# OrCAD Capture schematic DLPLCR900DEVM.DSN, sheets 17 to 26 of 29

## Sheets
17 P14-Master Ext Flash Intf: size A3
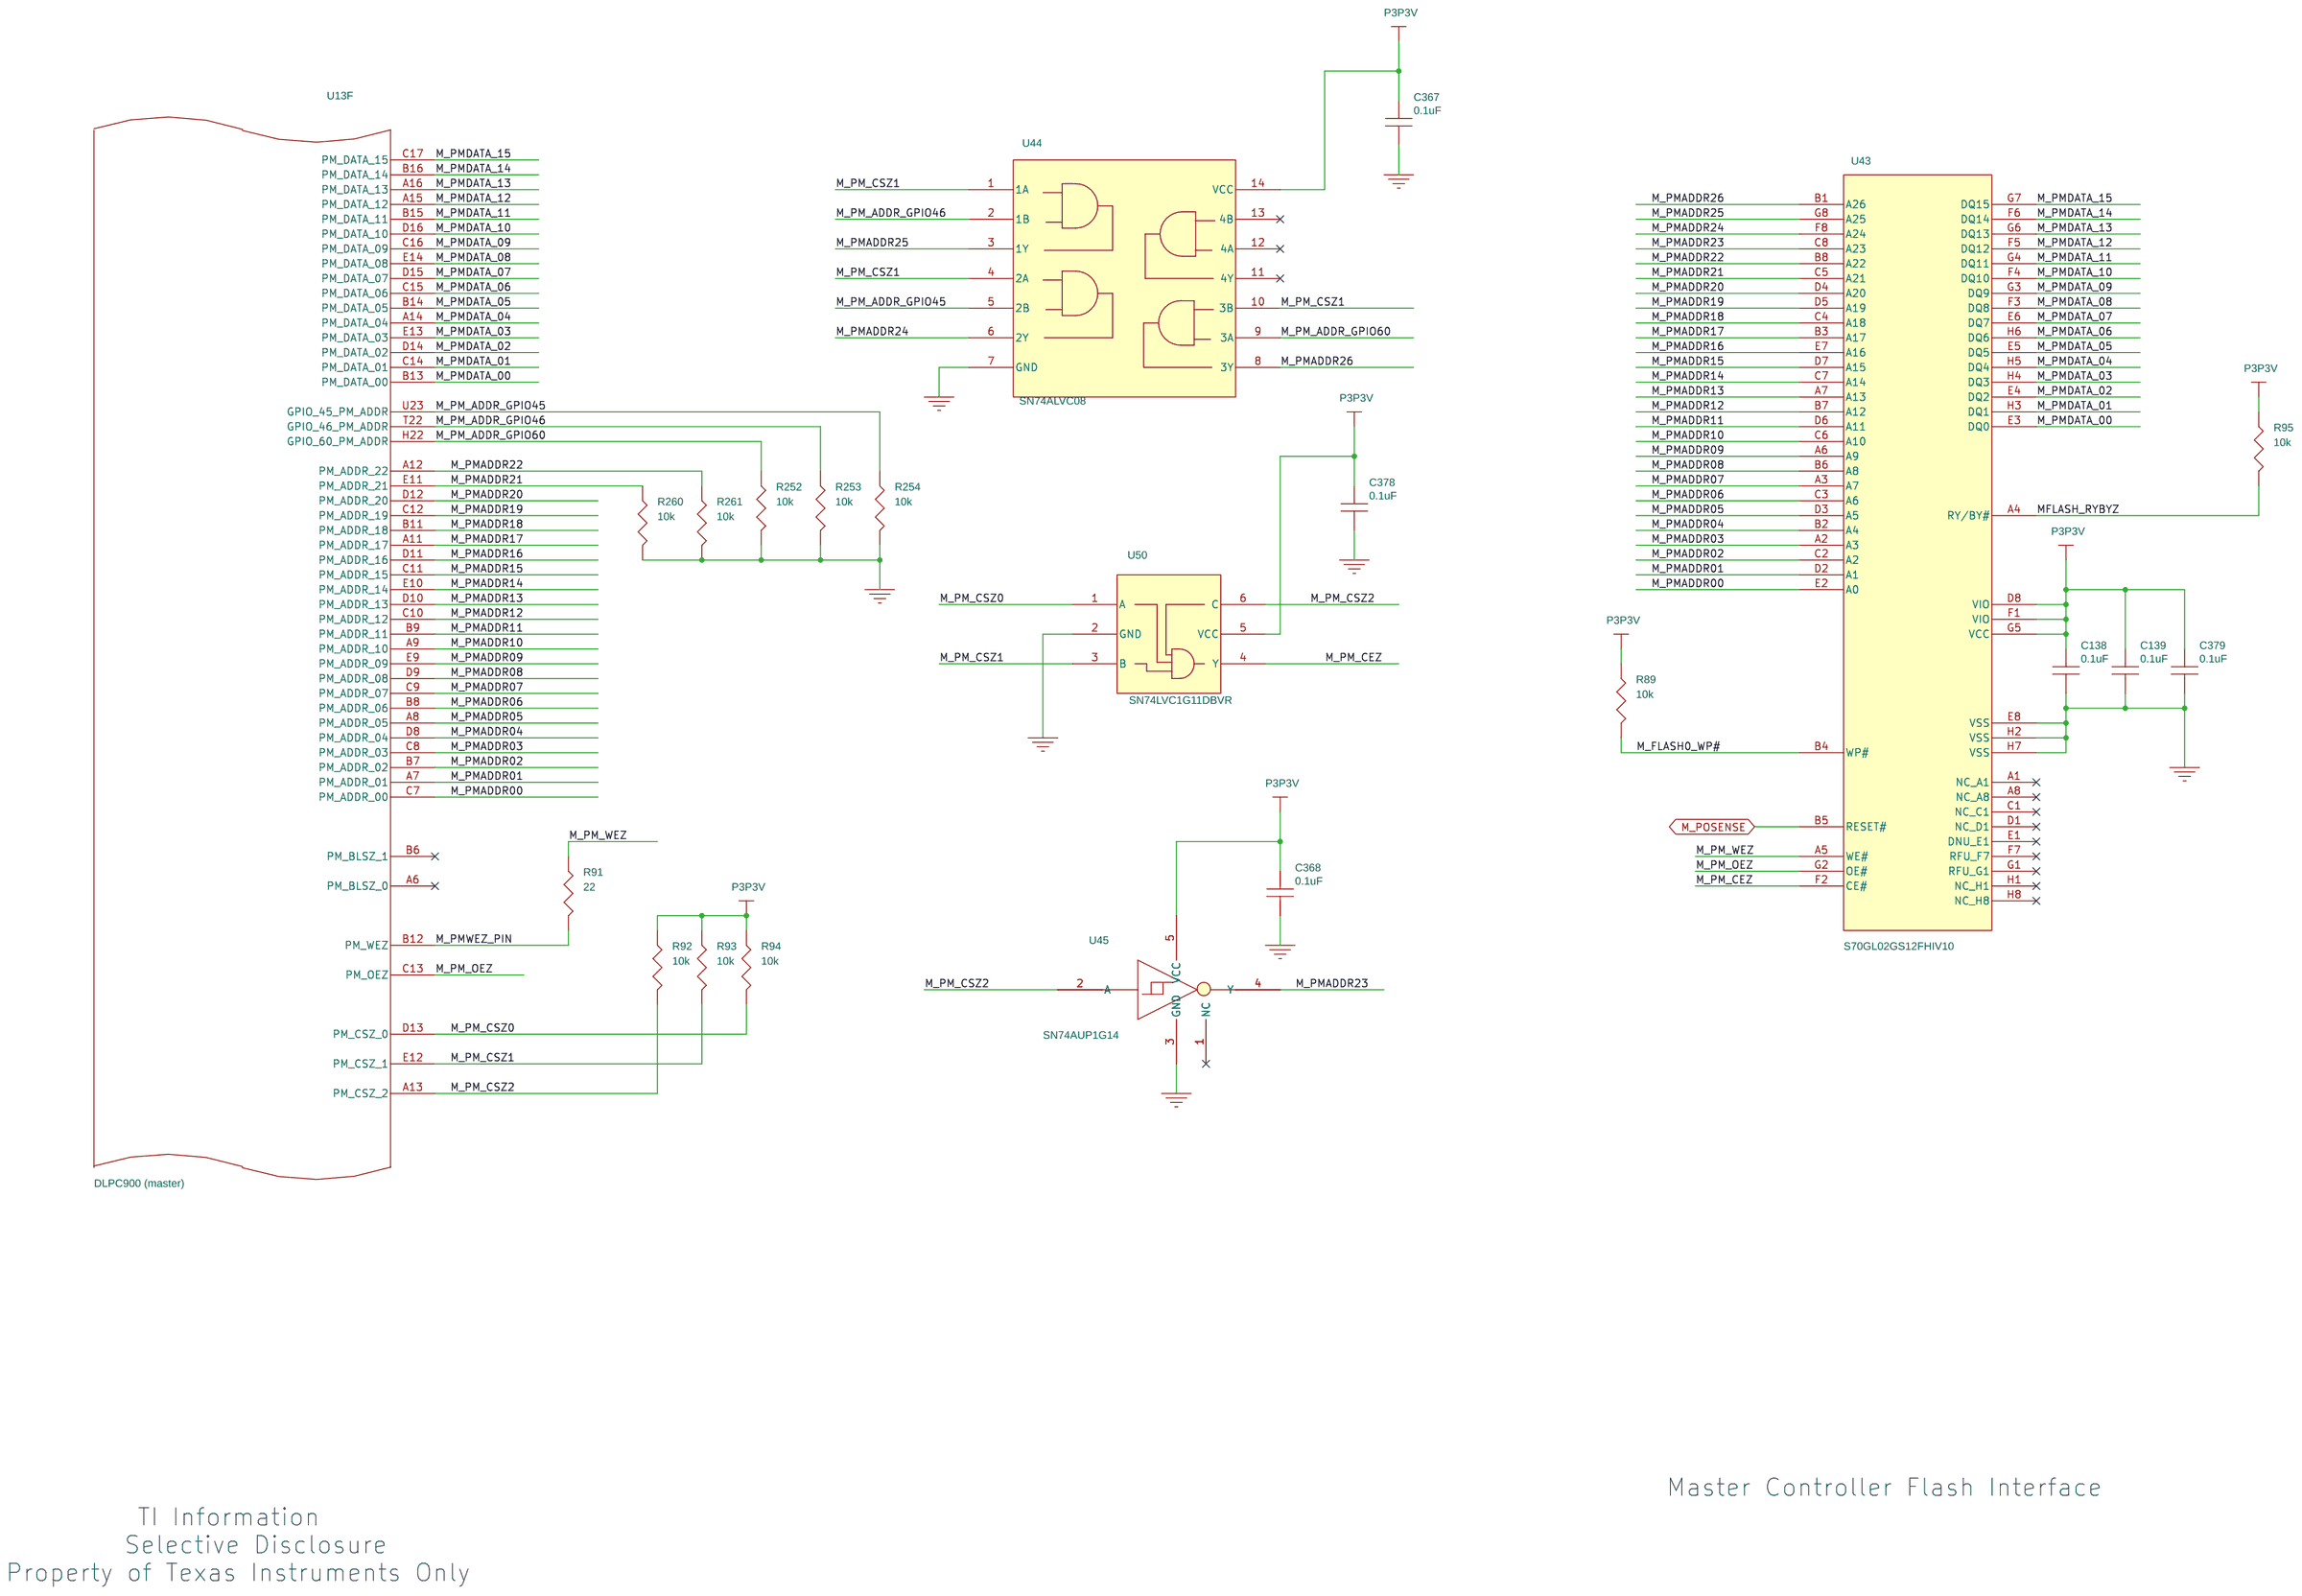
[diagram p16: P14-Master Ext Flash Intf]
18 P13-Master USB Osc Rst SSP: size A3
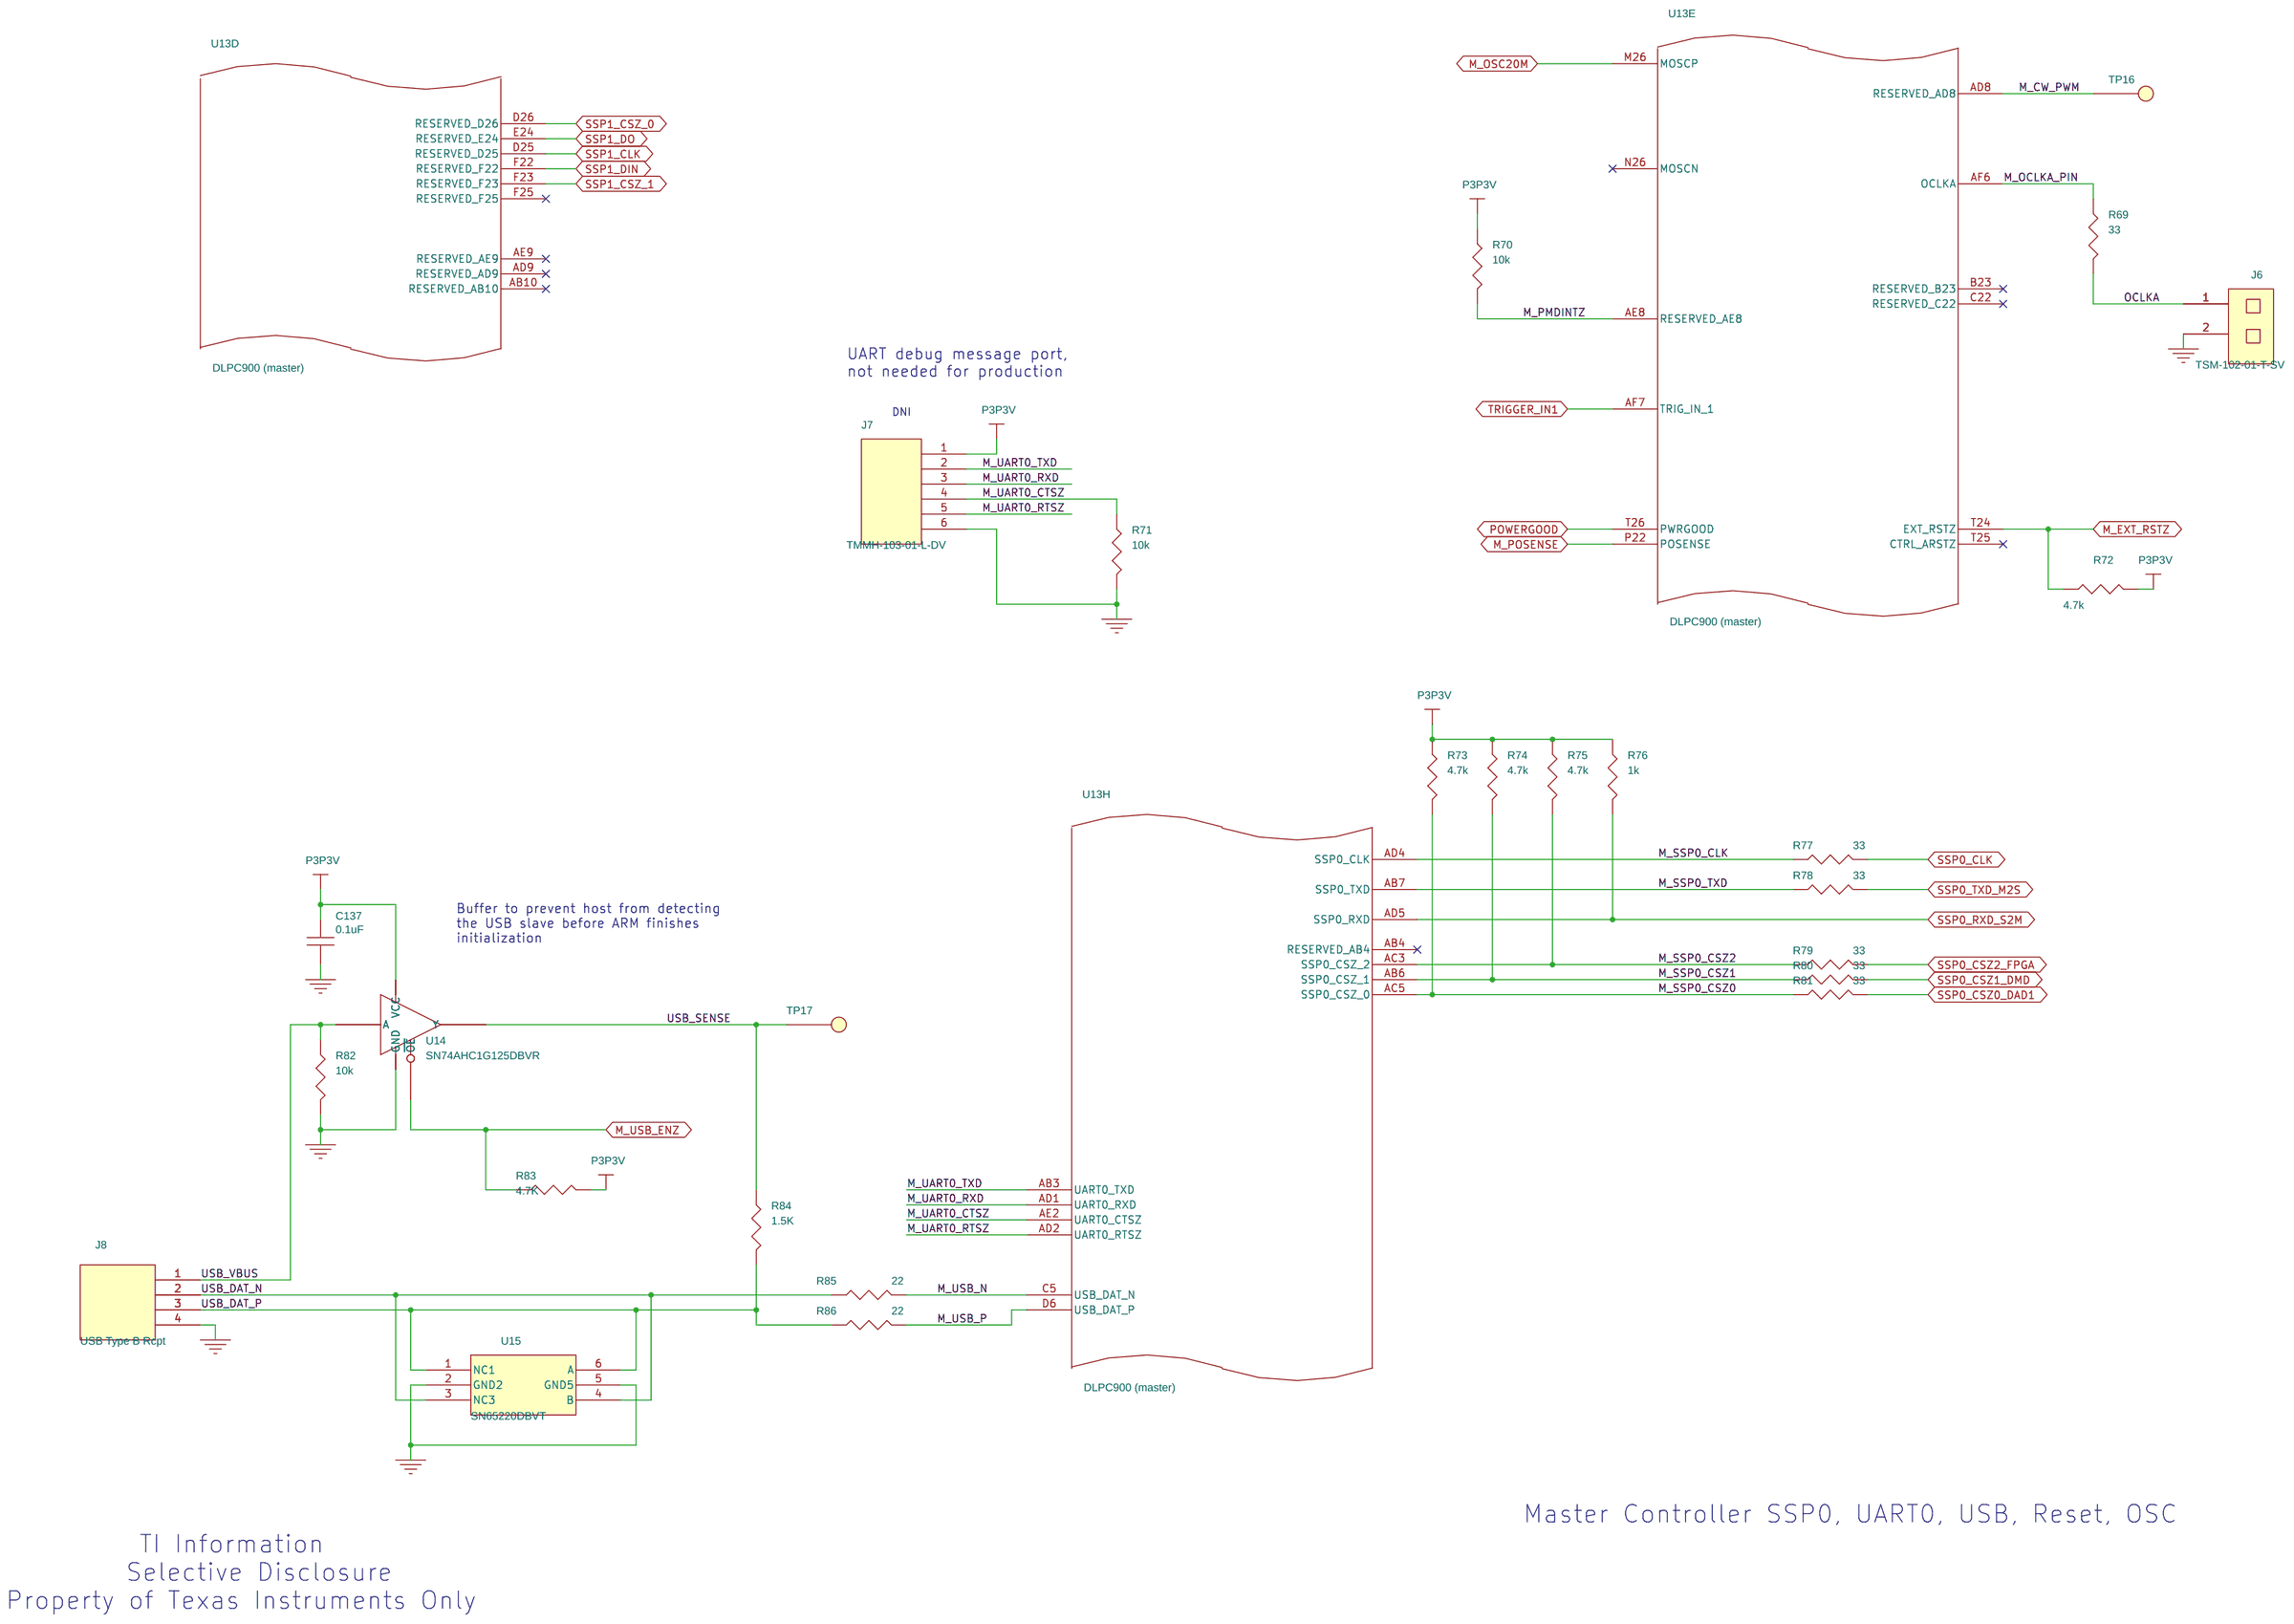
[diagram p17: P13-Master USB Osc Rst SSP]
19 P12-Master Vid DMD DAD io: size A3
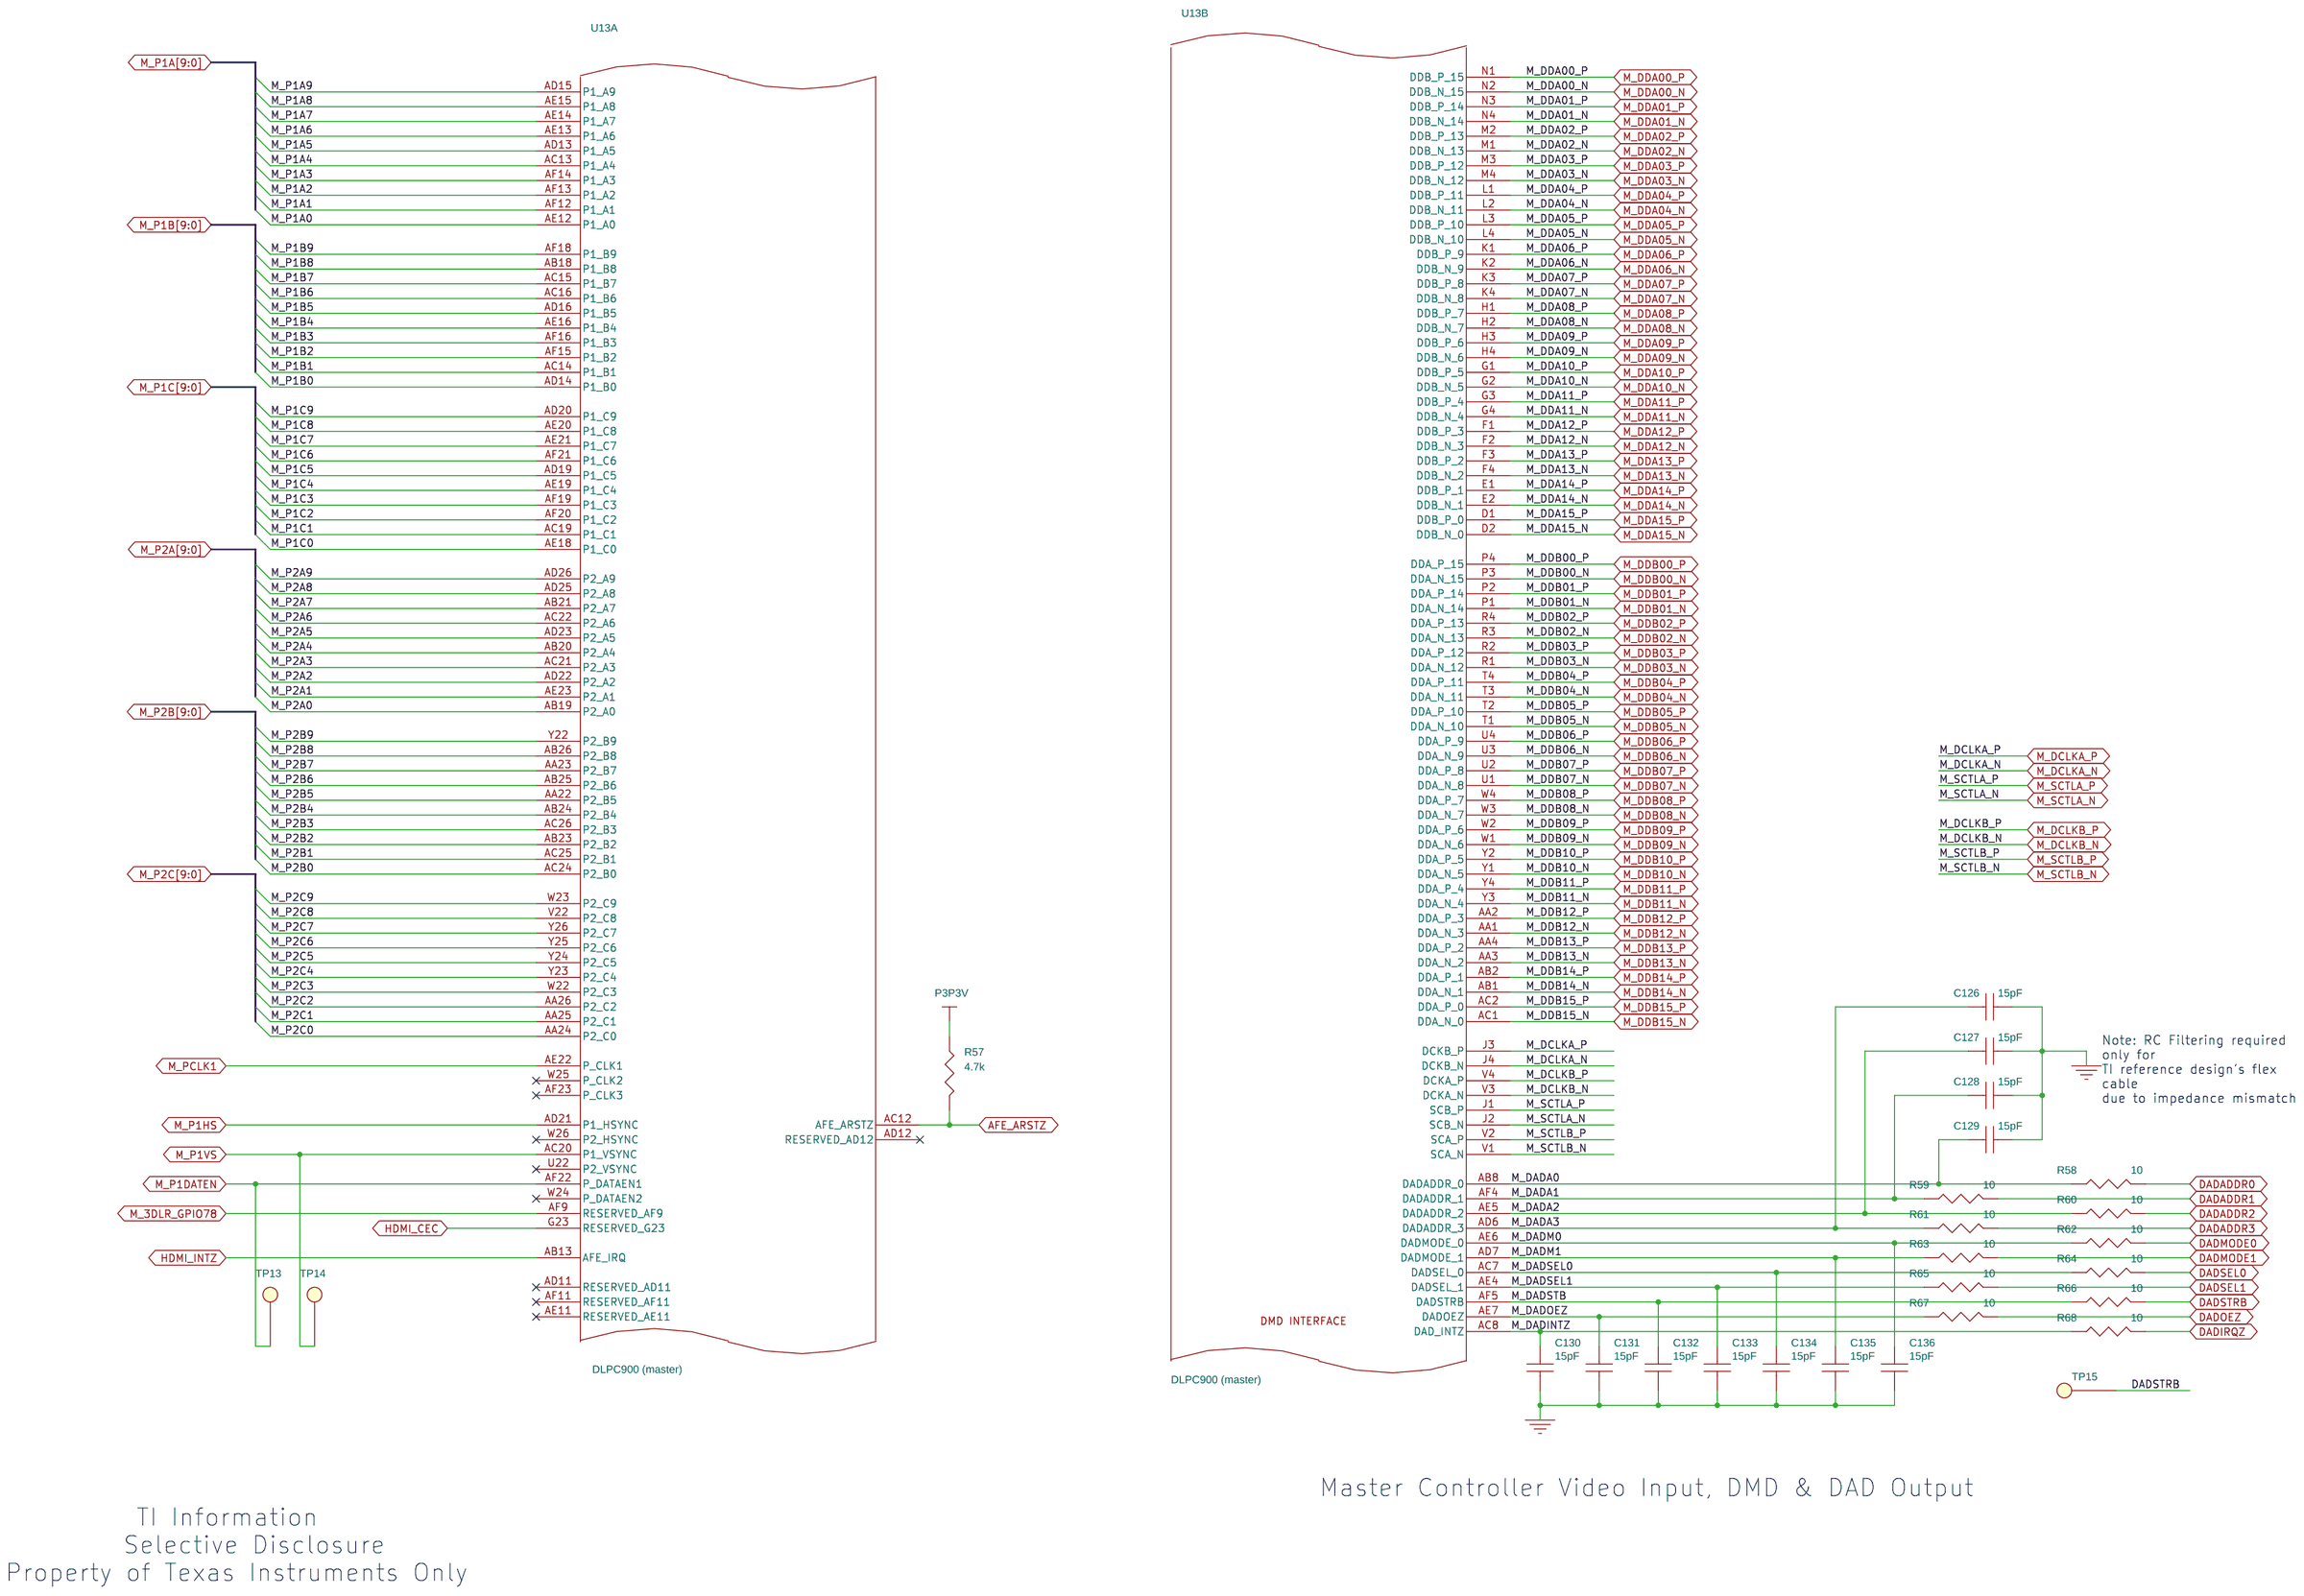
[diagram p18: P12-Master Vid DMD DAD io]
20 P01-Title
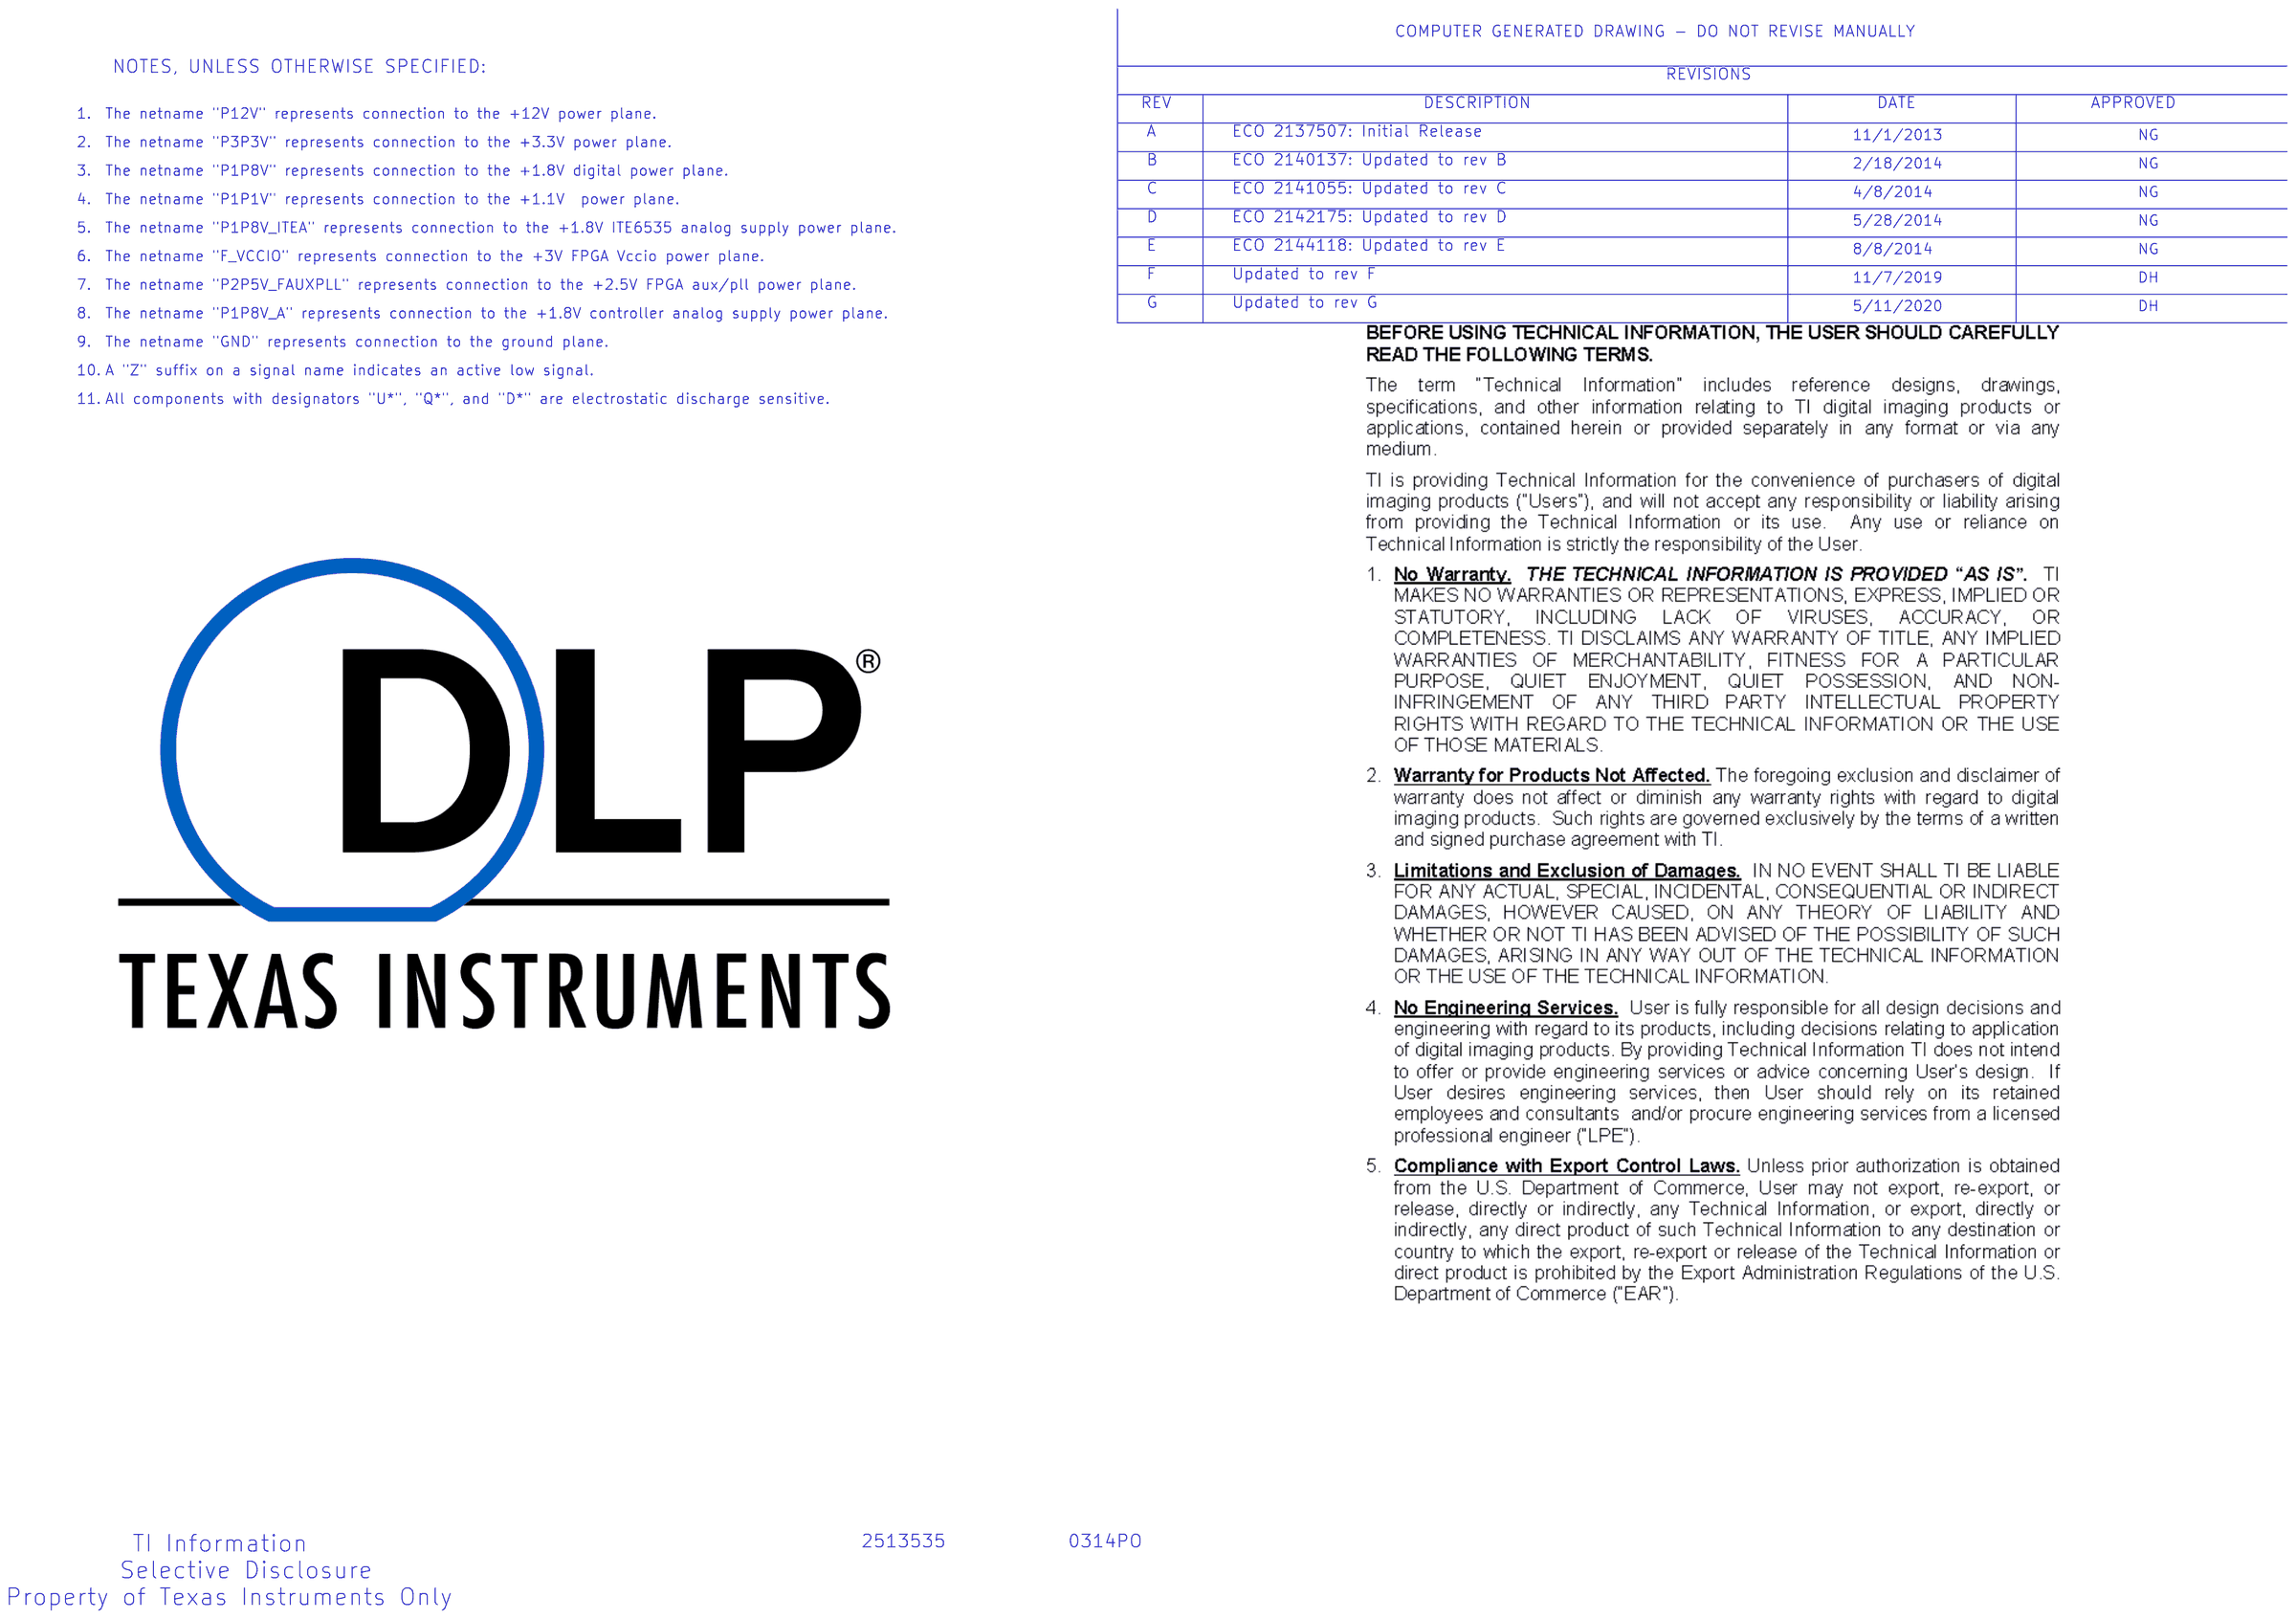
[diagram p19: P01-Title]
21 P03-Table Of Contents
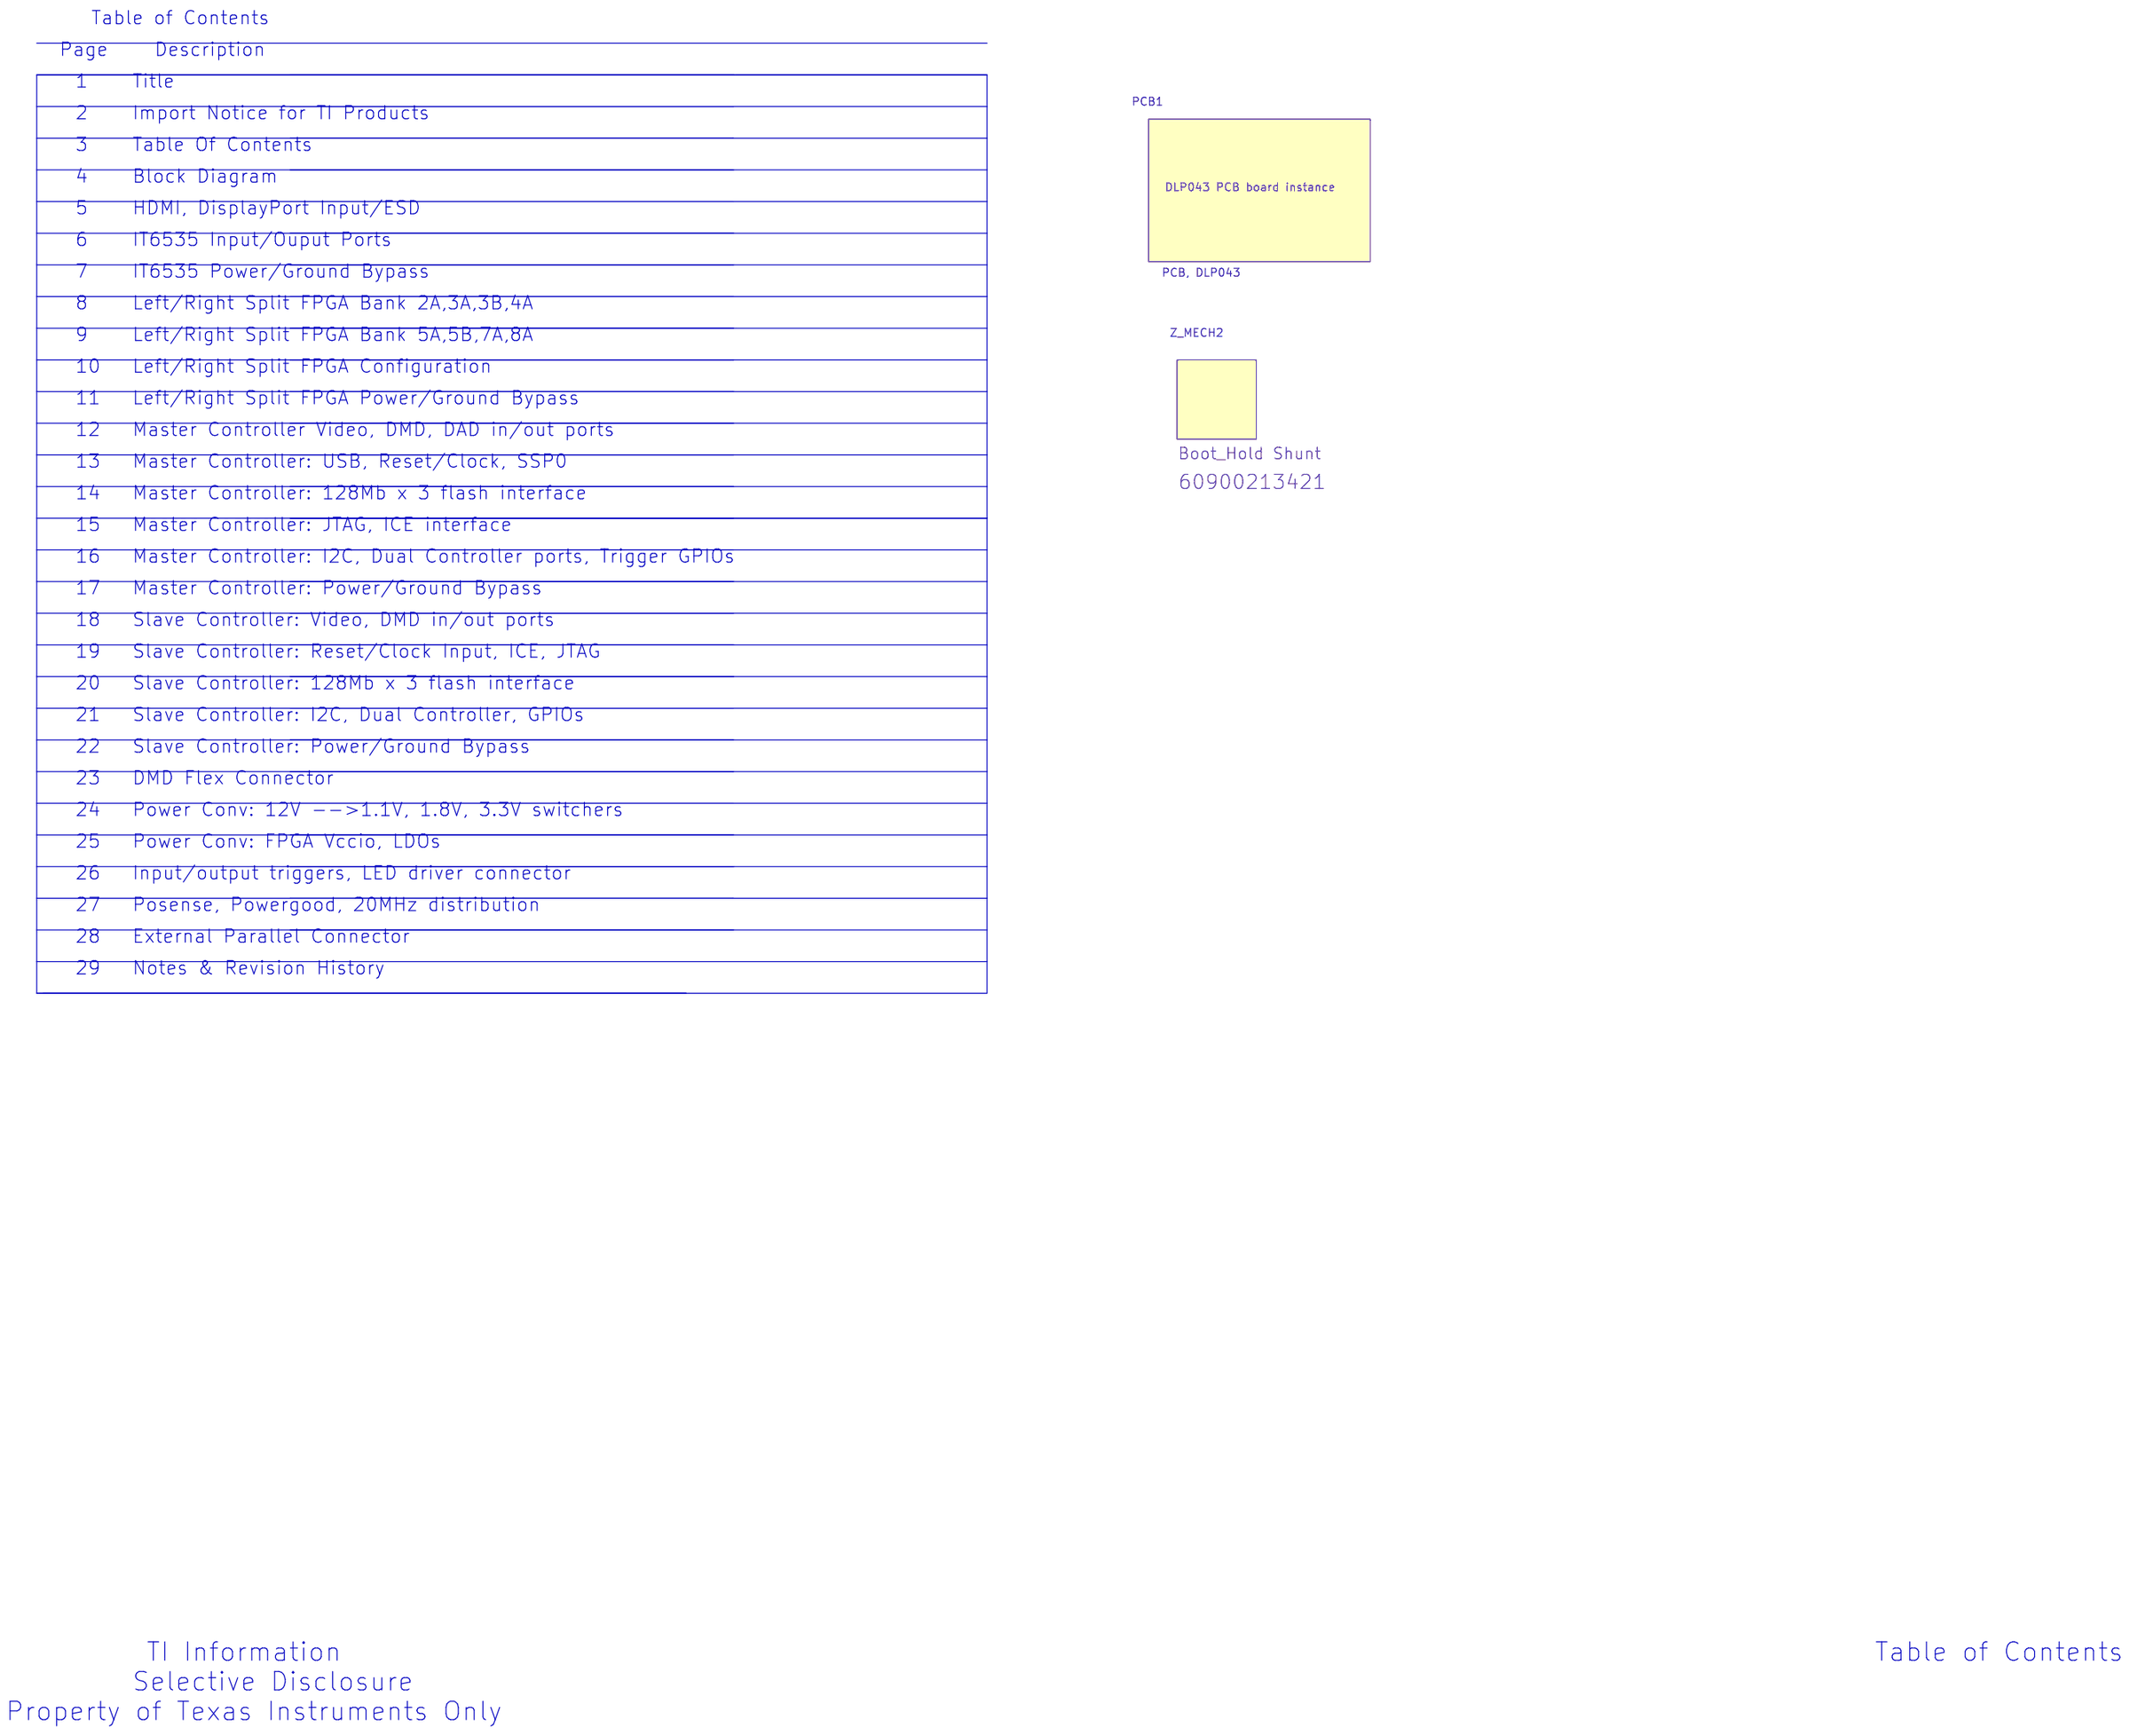
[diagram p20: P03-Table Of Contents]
22 P04-Block Diagram
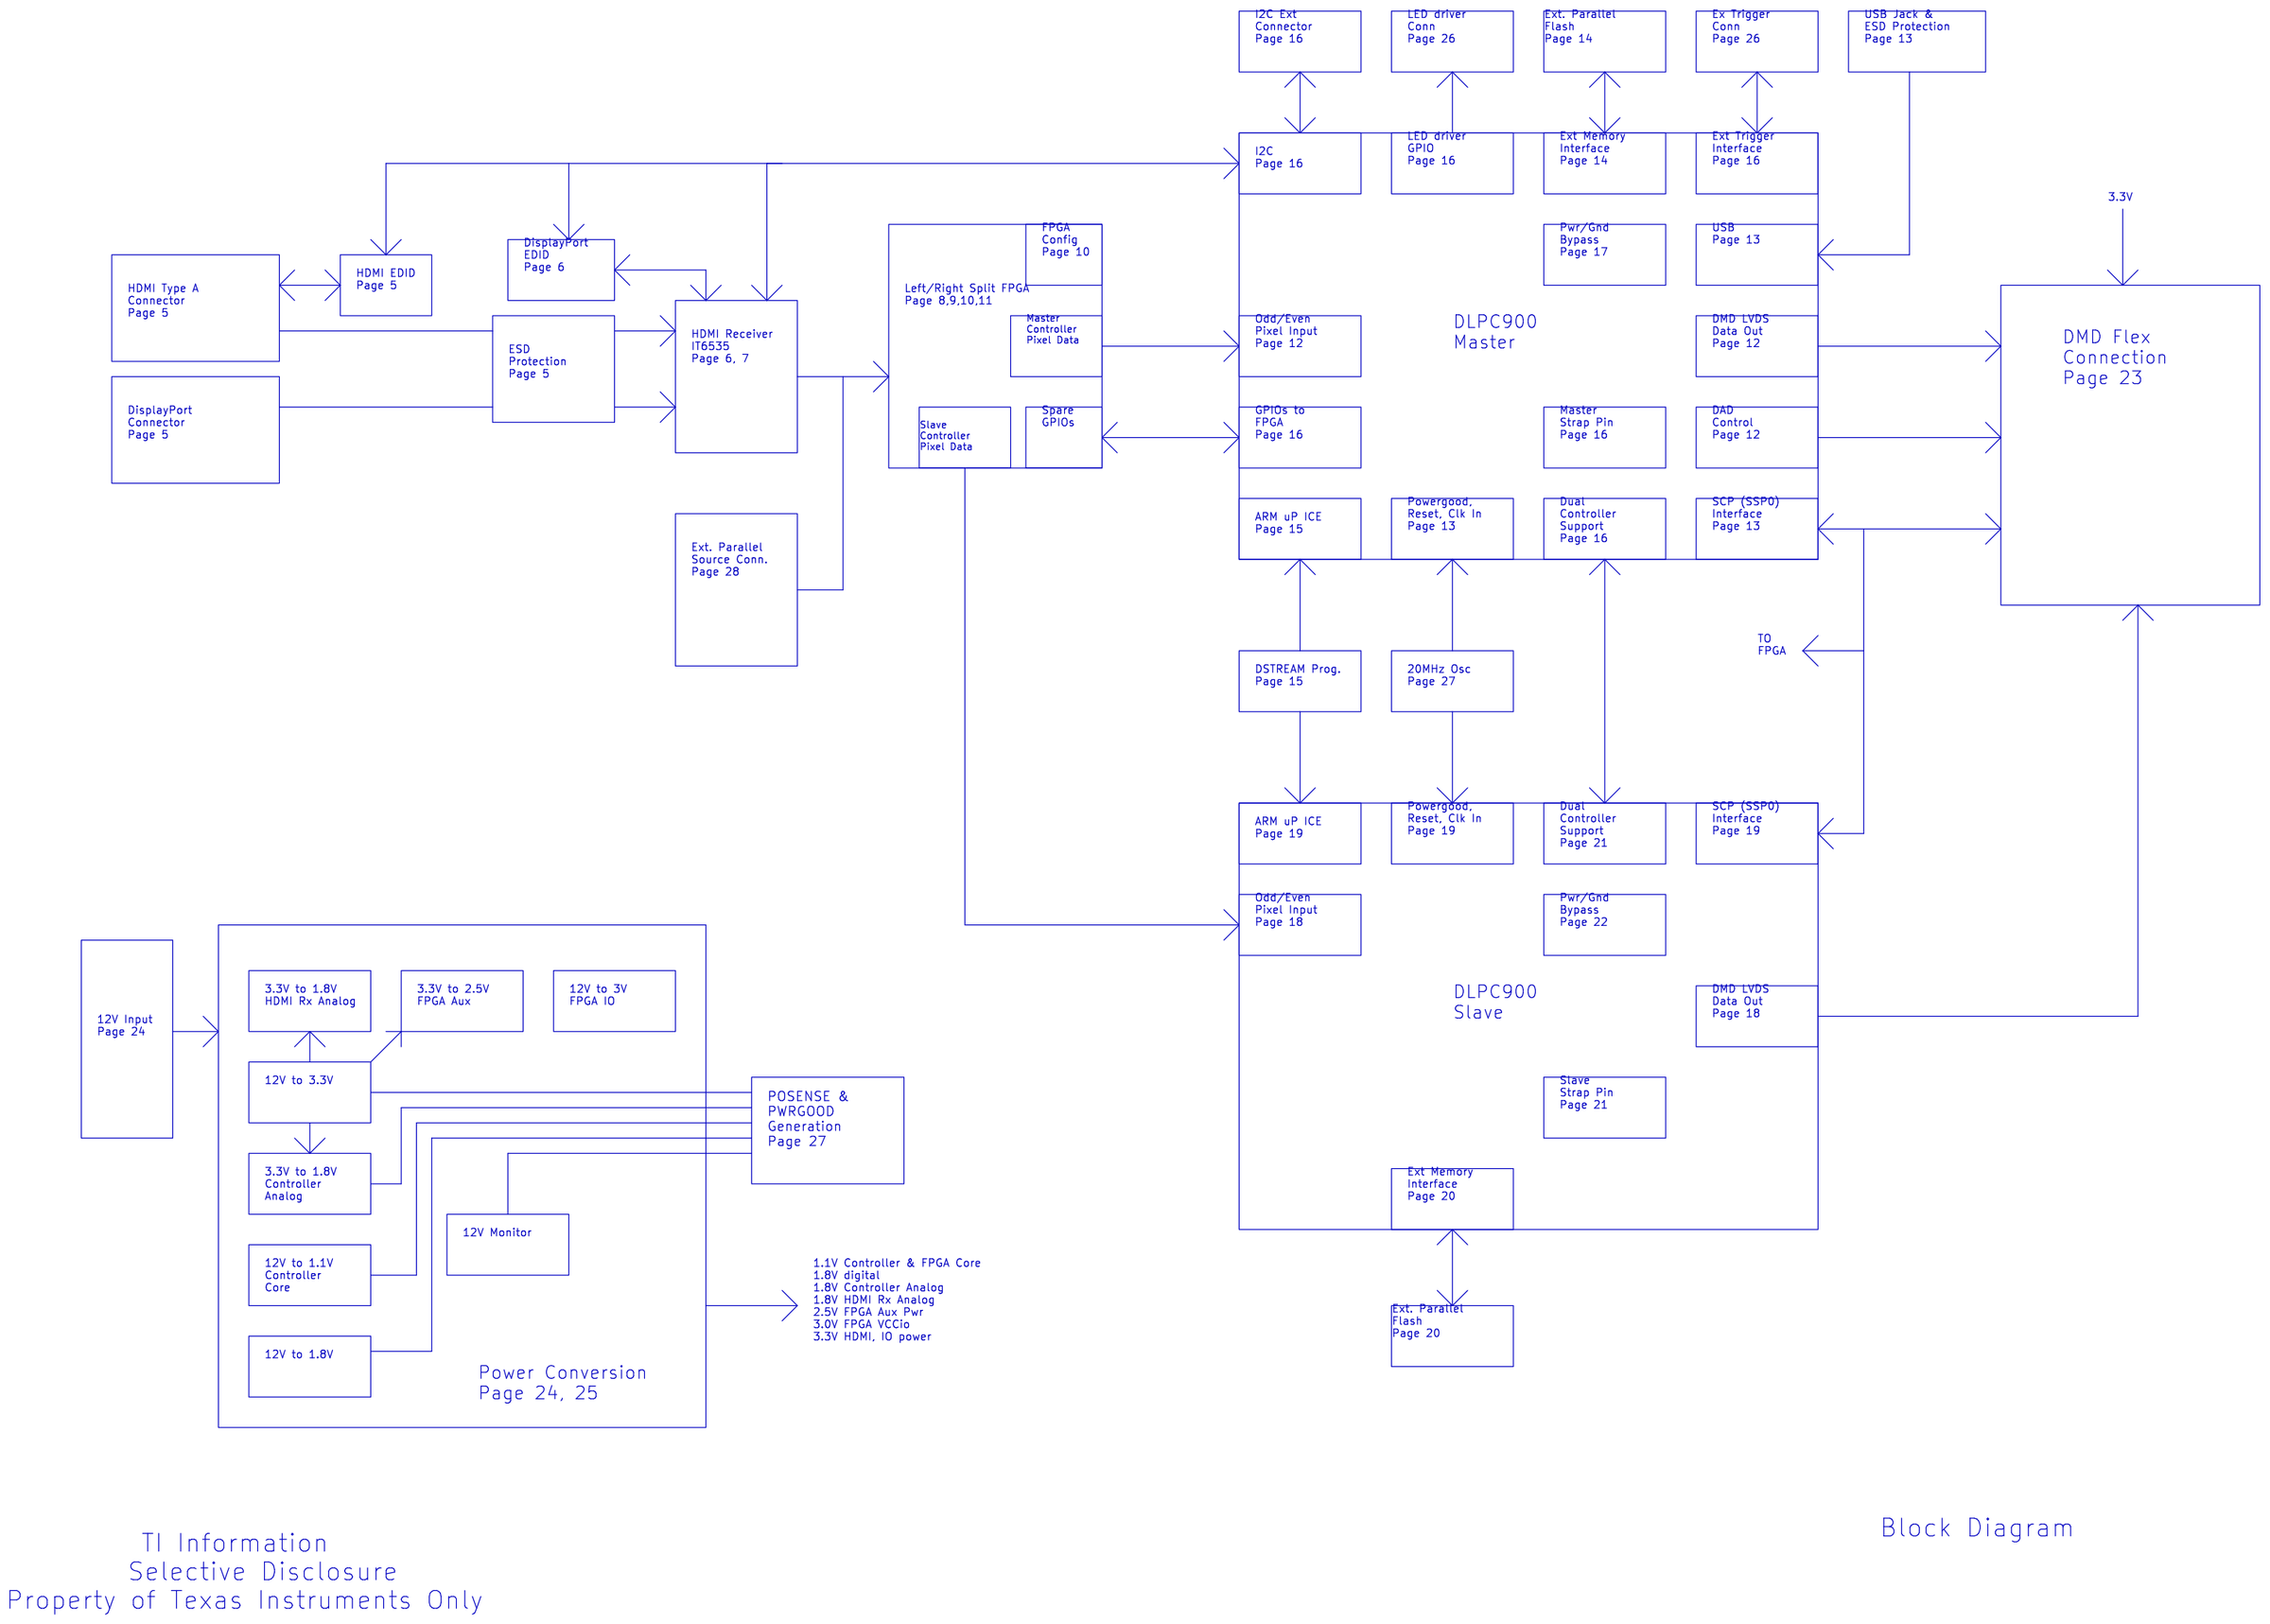
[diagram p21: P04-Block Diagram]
23 P06-IT6535 Input Output Ports: size A3
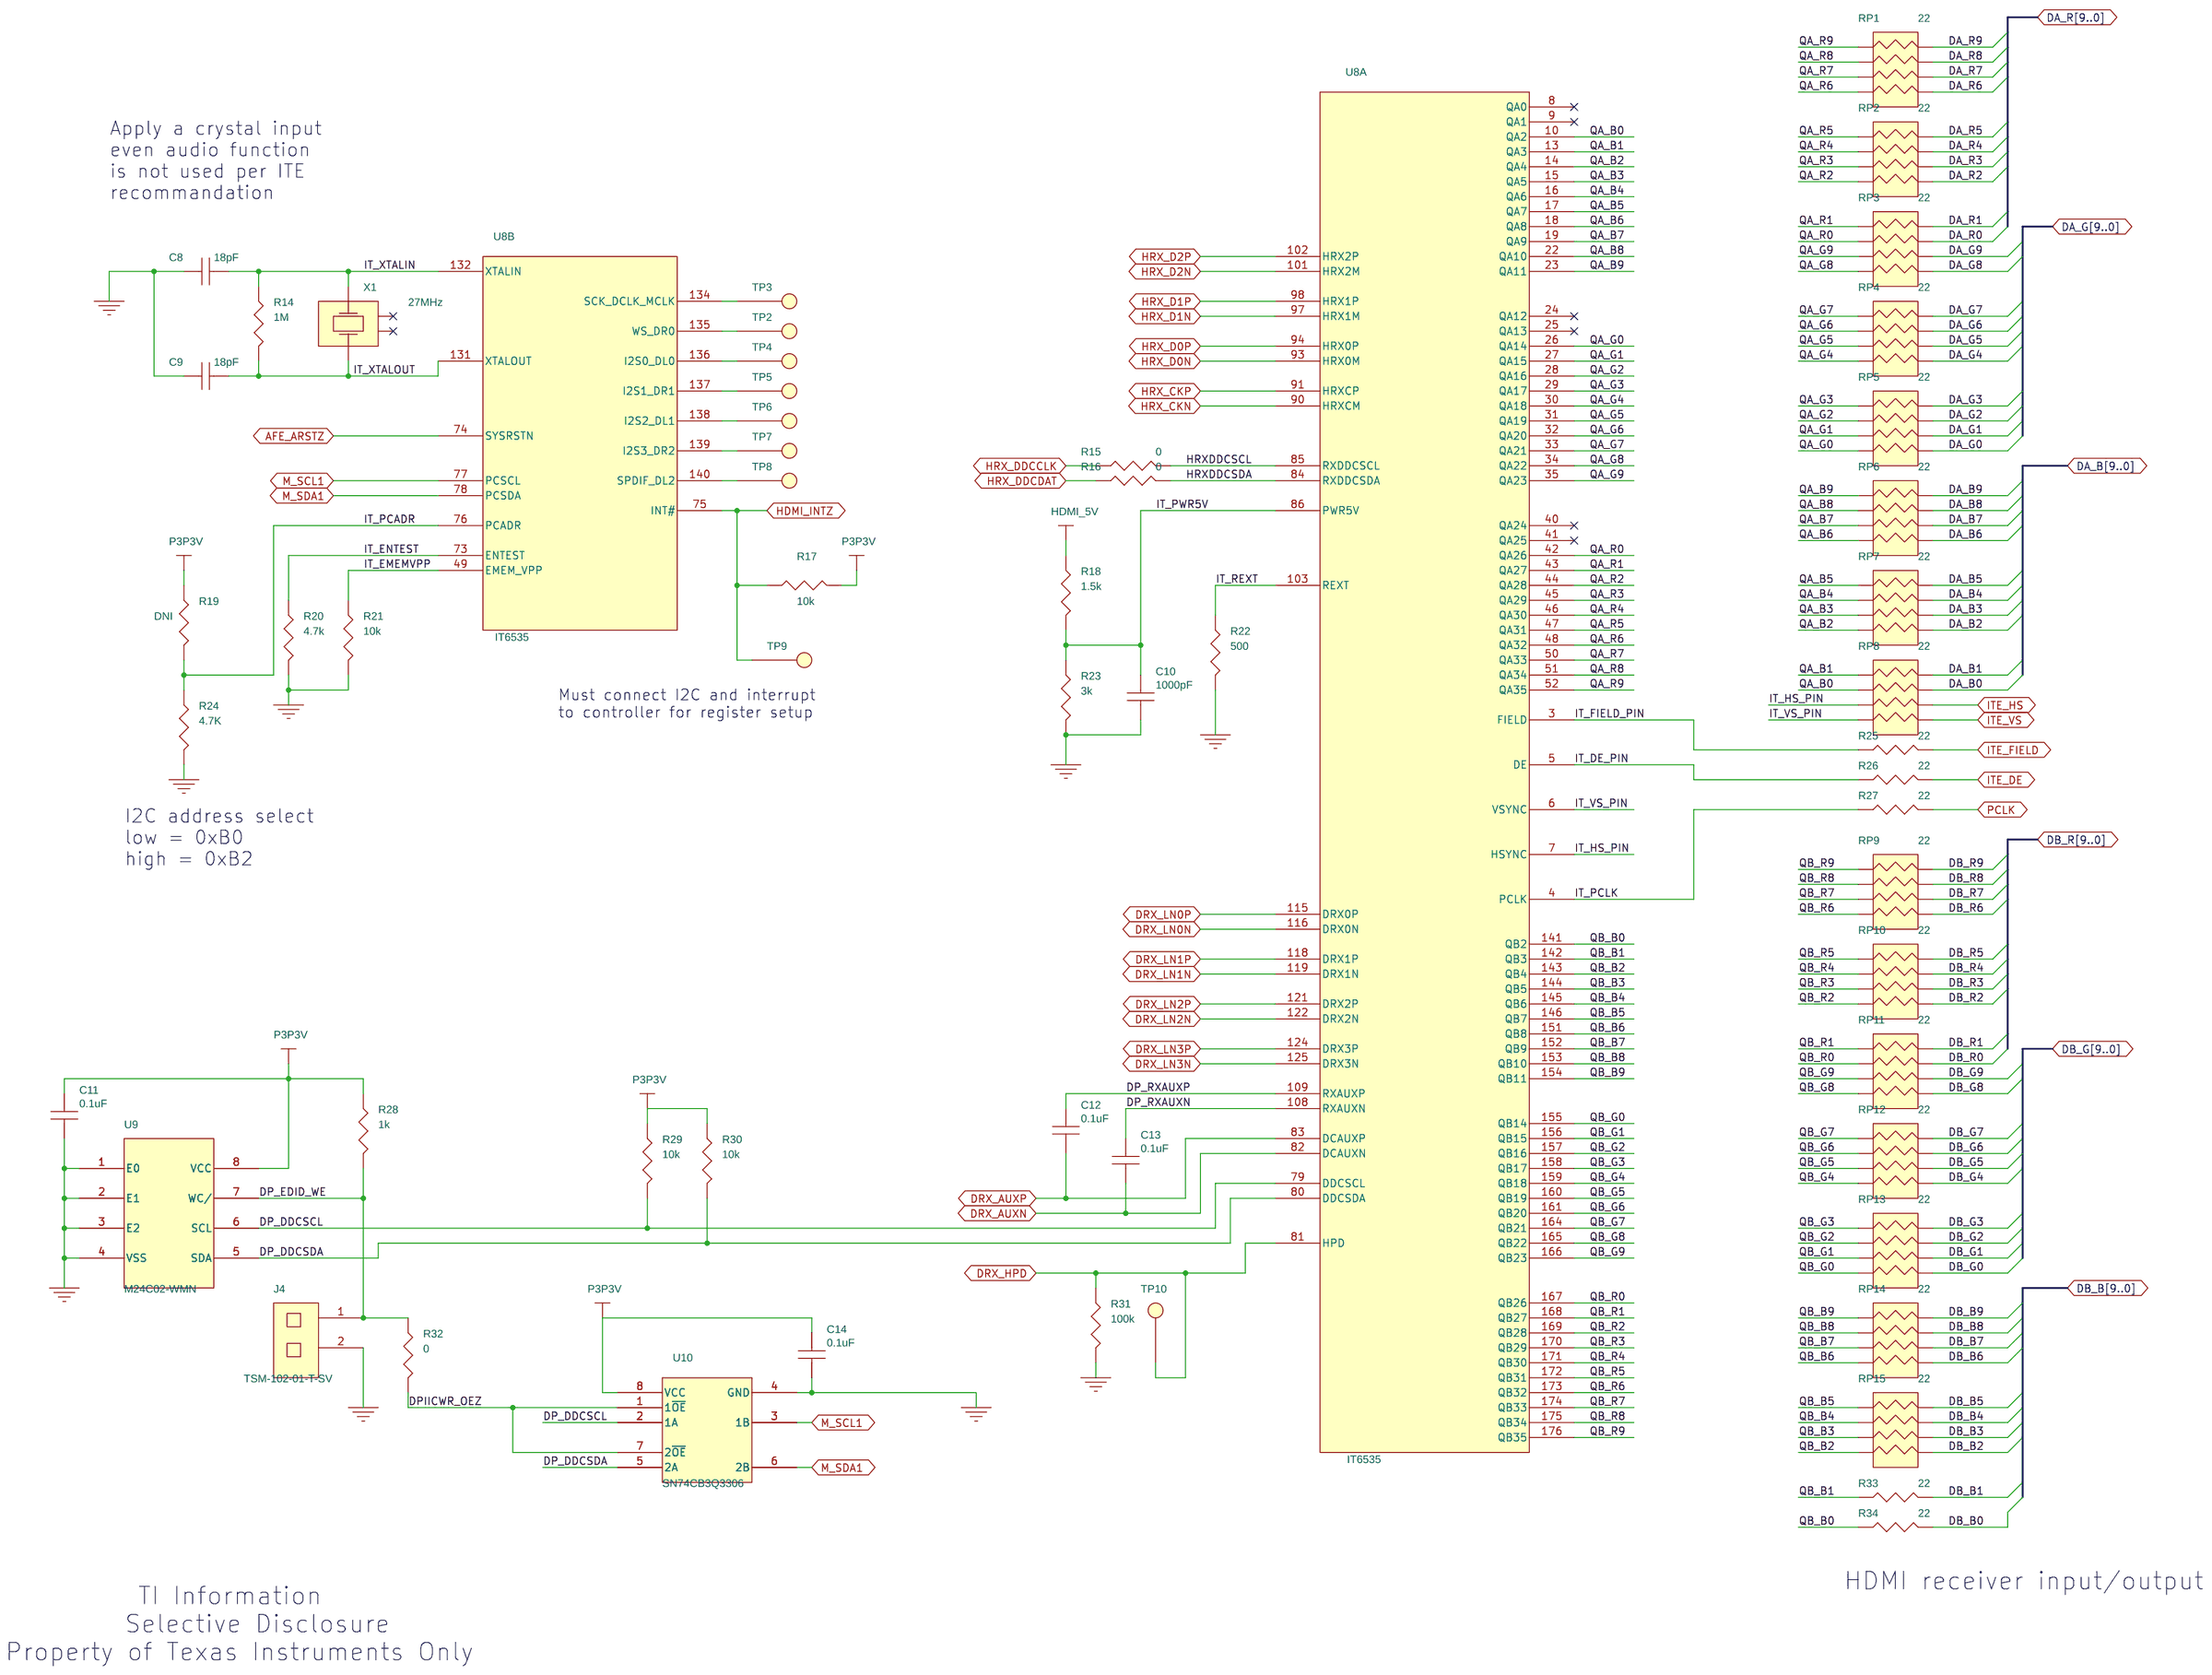
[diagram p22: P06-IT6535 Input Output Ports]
24 P29-Notes and Revision
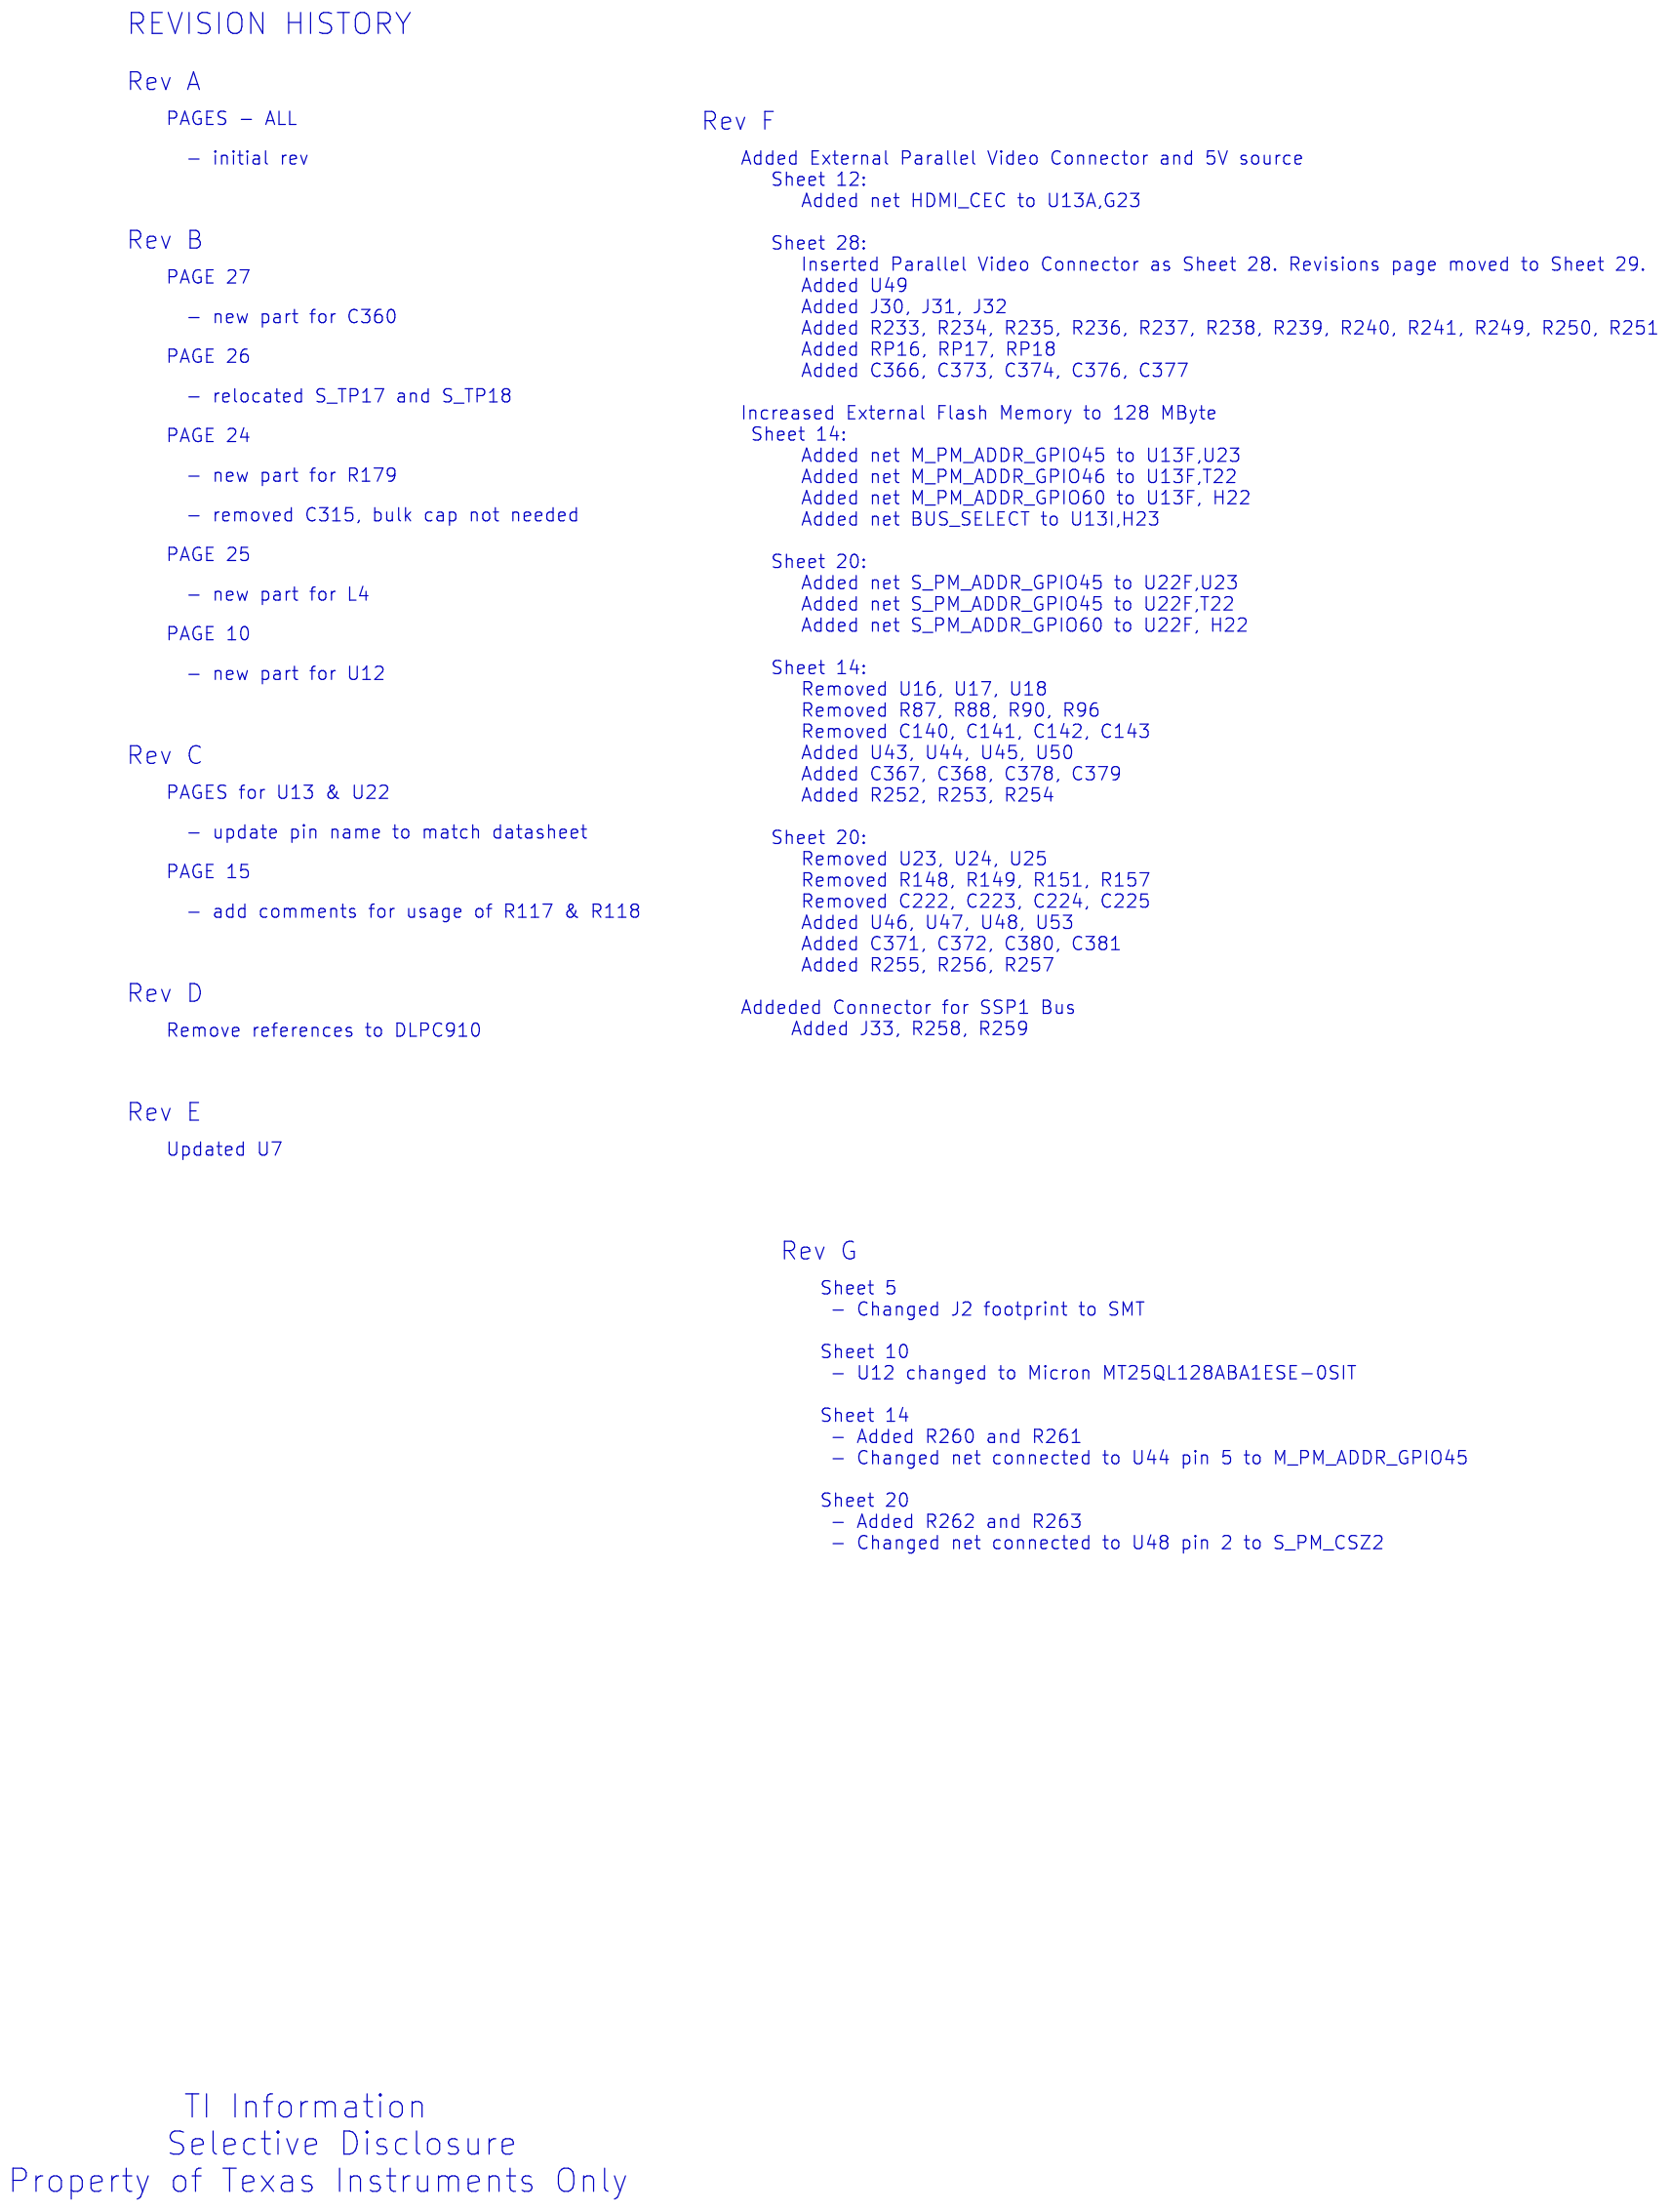
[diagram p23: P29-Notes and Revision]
25 P07-IT6535 Pwr/Gnd: size A3
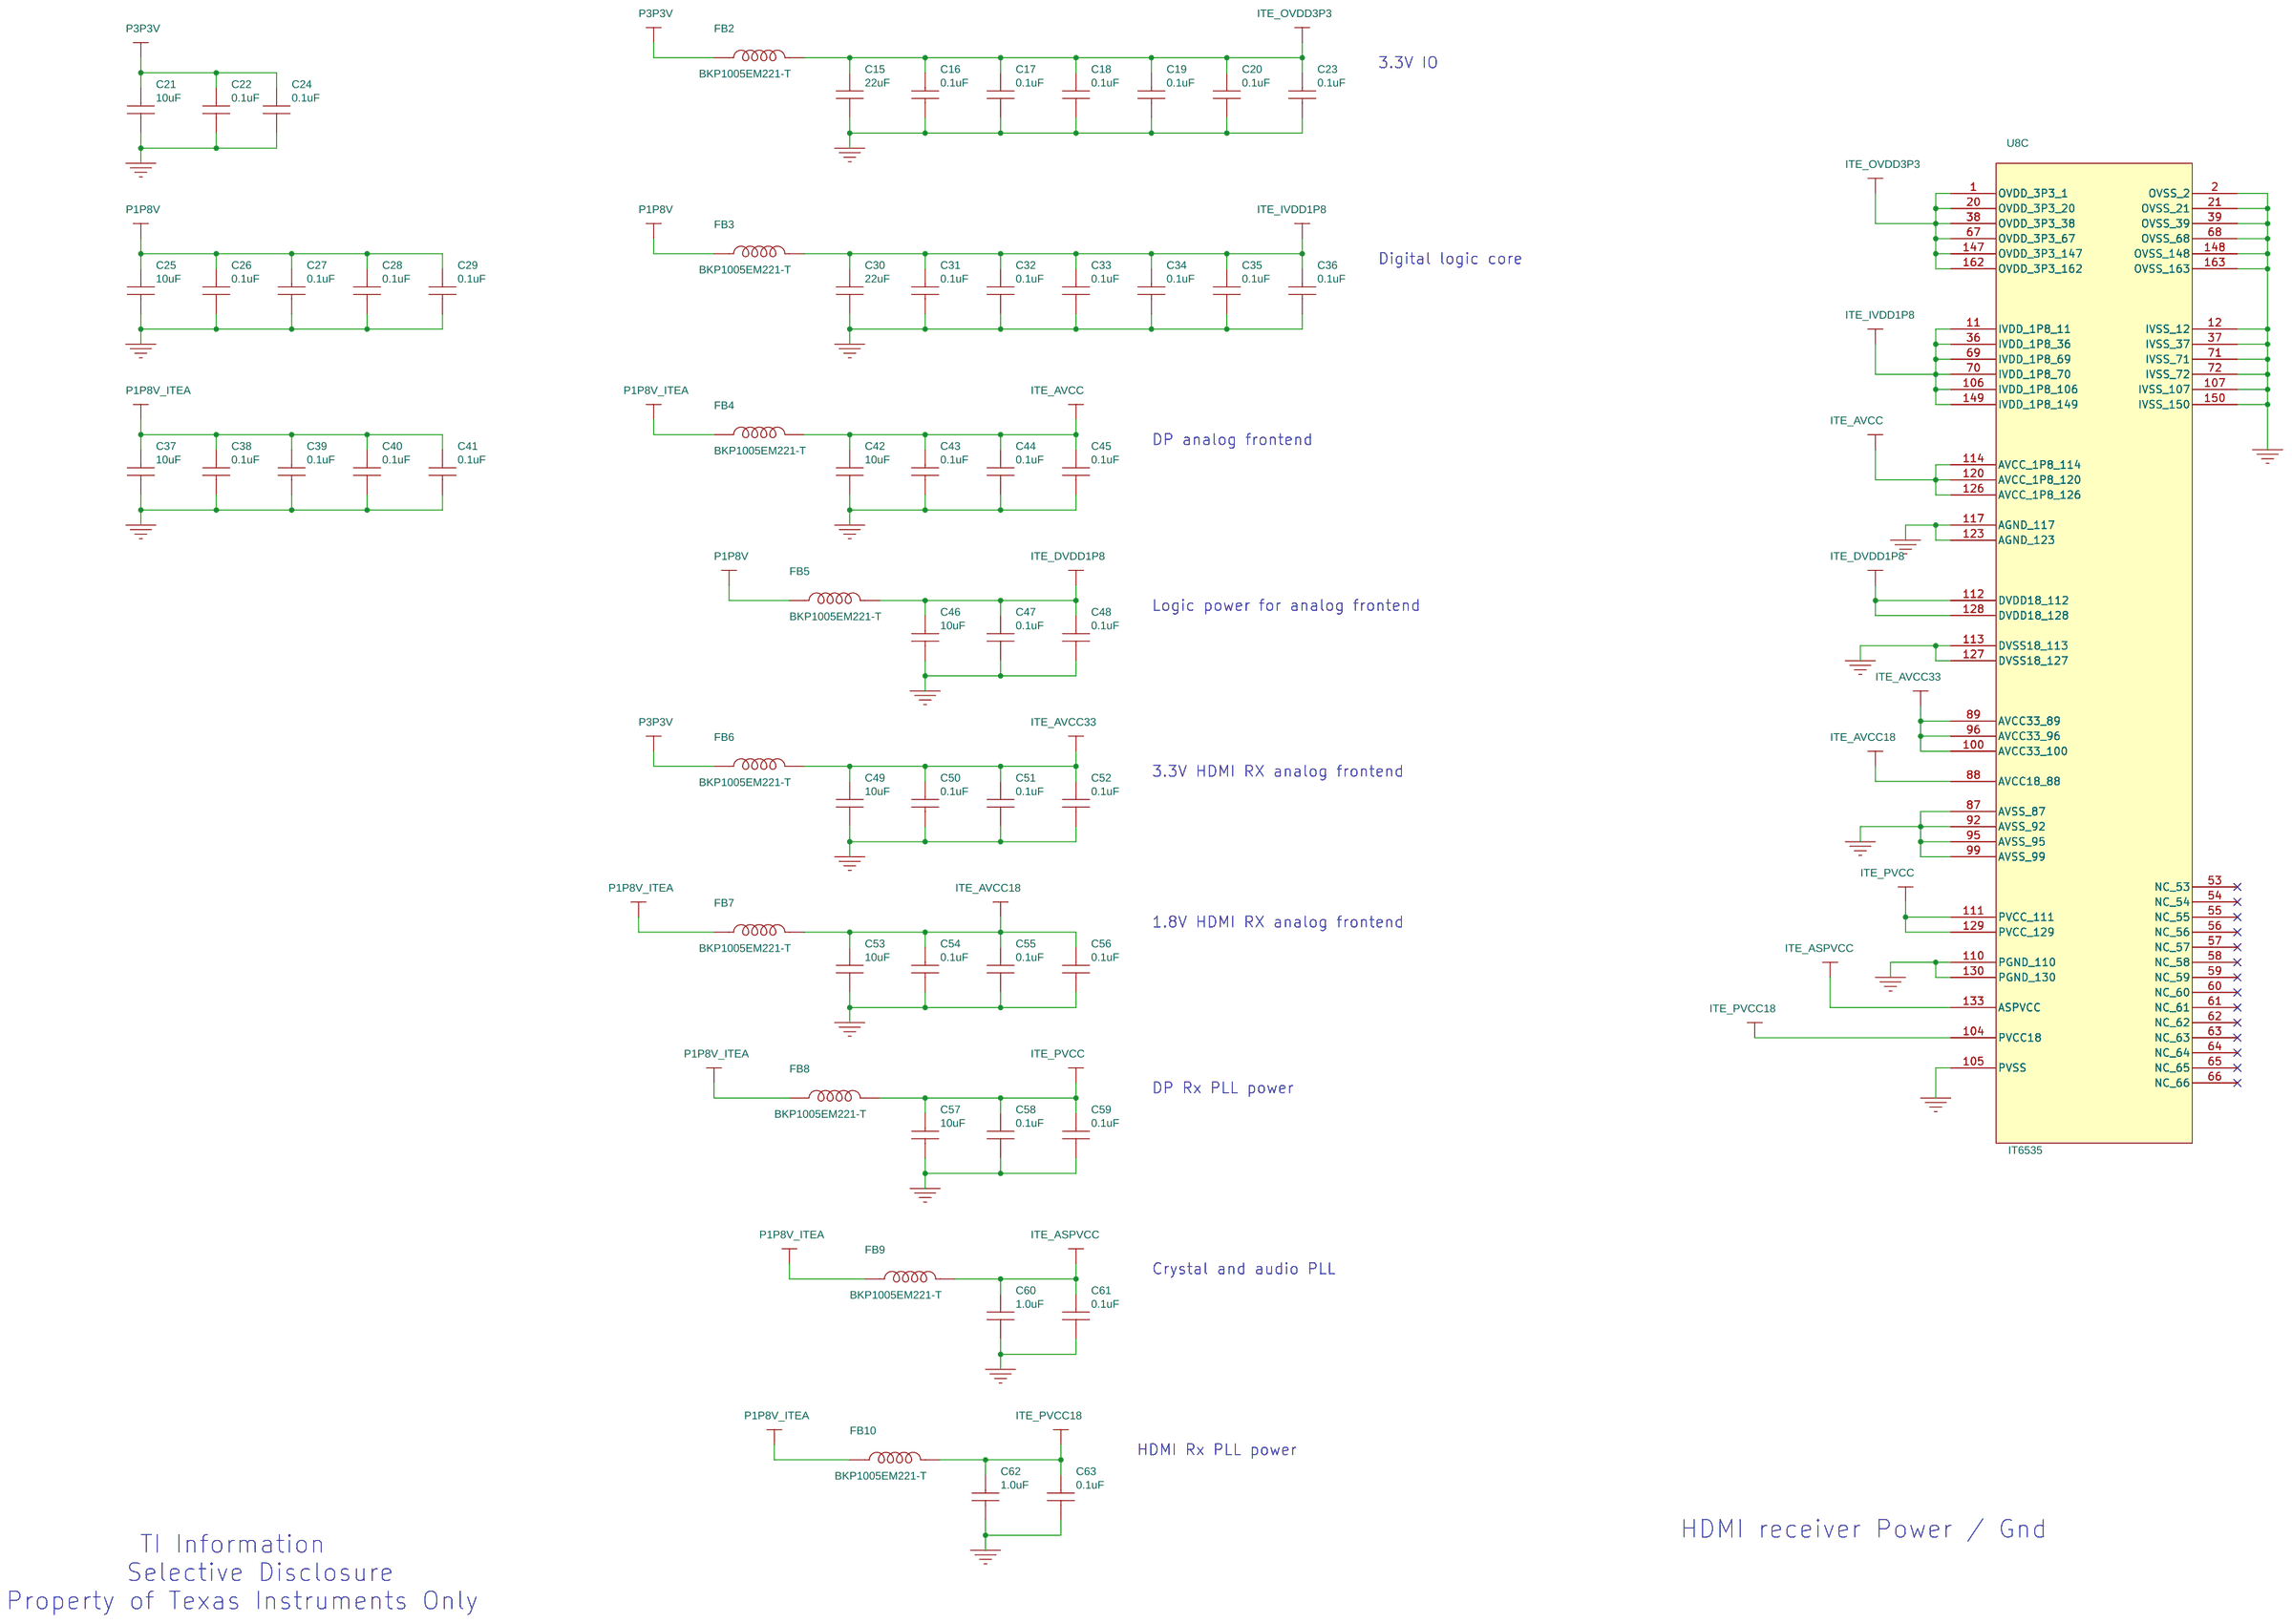
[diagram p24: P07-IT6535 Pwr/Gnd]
26 P11-FPGA Pwr/Gnd: size A3
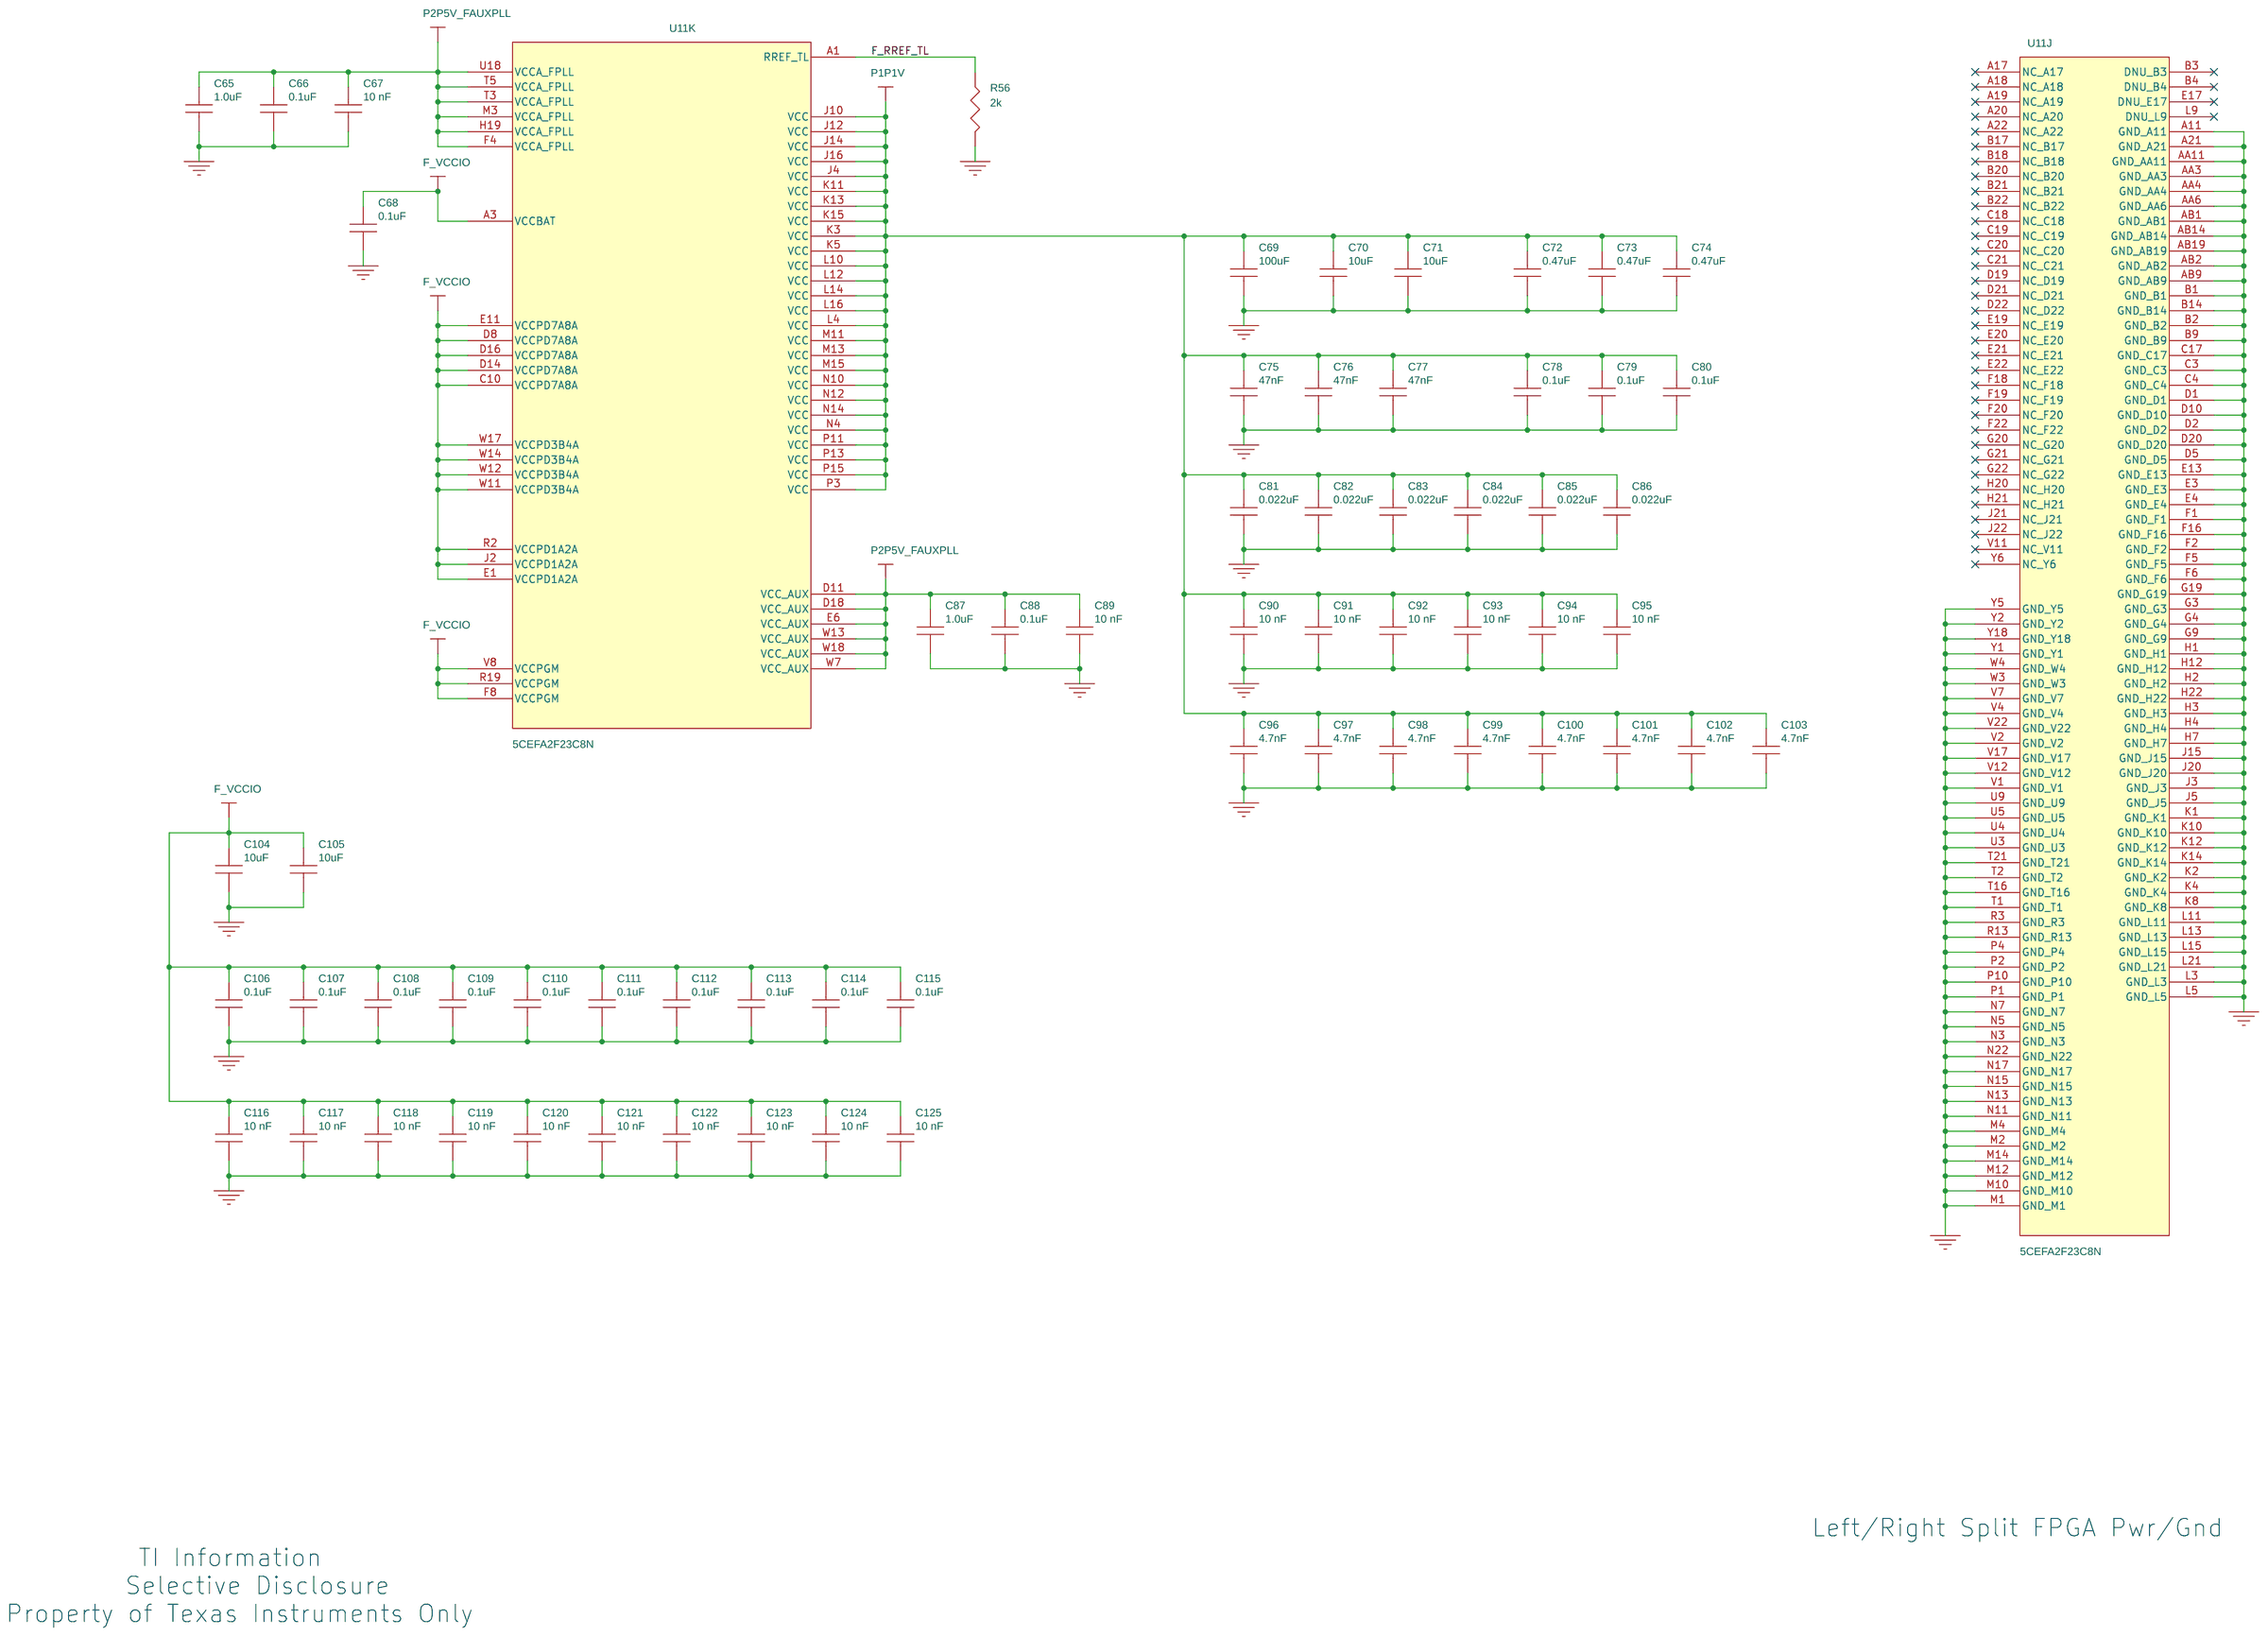
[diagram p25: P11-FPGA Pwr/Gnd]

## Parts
sheet P03-Table Of Contents
PCB1  PCB, DLP043
Z_MECH2  MECH
sheet P06-IT6535 Input Output Ports
C8  18pF  [0402]
C9  18pF  [0402]
C10  1000pF  [0402]
C11  0.1uF  [0402]
C12  0.1uF  [0402]
C13  0.1uF  [0402]
C14  0.1uF  [0402]
J4  TSM-102-01-T-SV  [2POS-2p54mm]
R14  1M  [0402]
R15  0  [0402]
R16  0  [0402]
R17  10k  [0402]
R18  1.5k  [0603]
R19  DNI  [0402]
R20  4.7k  [0402]
R21  10k  [0402]
R22  500  [0603]
R23  3k  [0402]
R24  4.7K  [0402]
R25  22  [0402]
R26  22  [0402]
R27  22  [0402]
R28  1k  [0402]
R29  10k  [0402]
R30  10k  [0402]
R31  100k  [0603]
R32  0  [0402]
R33  22  [0402]
R34  22  [0402]
RP1  22  [0804]
RP2  22  [0804]
RP3  22  [0804]
RP4  22  [0804]
RP5  22  [0804]
RP6  22  [0804]
RP7  22  [0804]
RP8  22  [0804]
RP9  22  [0804]
RP10  22  [0804]
RP11  22  [0804]
RP12  22  [0804]
RP13  22  [0804]
RP14  22  [0804]
RP15  22  [0804]
TP2  Testpoint  [24mil-plated]
TP3  Testpoint  [24mil-plated]
TP4  Testpoint  [24mil-plated]
TP5  Testpoint  [24mil-plated]
TP6  Testpoint  [24mil-plated]
TP7  Testpoint  [24mil-plated]
TP8  Testpoint  [24mil-plated]
TP9  Testpoint  [24mil-plated]
TP10  Testpoint  [24mil-plated]
U9  M24C02-WMN  [SO8]
U10  SN74CB3Q3306  [8TSSOP]
X1  27MHz  [4SMD]
sheet P07-IT6535 Pwr/Gnd
C15  22uF  [0805]
C16  0.1uF  [0402]
C17  0.1uF  [0402]
C18  0.1uF  [0402]
C19  0.1uF  [0402]
C20  0.1uF  [0402]
C21  10uF  [0603]
C22  0.1uF  [0402]
C23  0.1uF  [0402]
C24  0.1uF  [0402]
C25  10uF  [0603]
C26  0.1uF  [0402]
C27  0.1uF  [0402]
C28  0.1uF  [0402]
C29  0.1uF  [0402]
C30  22uF  [0805]
C31  0.1uF  [0402]
C32  0.1uF  [0402]
C33  0.1uF  [0402]
C34  0.1uF  [0402]
C35  0.1uF  [0402]
C36  0.1uF  [0402]
C37  10uF  [0603]
C38  0.1uF  [0402]
C39  0.1uF  [0402]
C40  0.1uF  [0402]
C41  0.1uF  [0402]
C42  10uF  [0603]
C43  0.1uF  [0402]
C44  0.1uF  [0402]
C45  0.1uF  [0402]
C46  10uF  [0603]
C47  0.1uF  [0402]
C48  0.1uF  [0402]
C49  10uF  [0603]
C50  0.1uF  [0402]
C51  0.1uF  [0402]
C52  0.1uF  [0402]
C53  10uF  [0603]
C54  0.1uF  [0402]
C55  0.1uF  [0402]
C56  0.1uF  [0402]
C57  10uF  [0603]
C58  0.1uF  [0402]
C59  0.1uF  [0402]
C60  1.0uF  [0402]
C61  0.1uF  [0402]
C62  1.0uF  [0402]
C63  0.1uF  [0402]
FB2  BKP1005EM221-T  [0402]
FB3  BKP1005EM221-T  [0402]
FB4  BKP1005EM221-T  [0402]
FB5  BKP1005EM221-T  [0402]
FB6  BKP1005EM221-T  [0402]
FB7  BKP1005EM221-T  [0402]
FB8  BKP1005EM221-T  [0402]
FB9  BKP1005EM221-T  [0402]
FB10  BKP1005EM221-T  [0402]
U8  IT6535  [TQFP-176]  (sections A,B,C)
sheet P10-FPGA Config
U11  5CEFA2F23C8N  [F484]  (sections A,B,C,D,E,F,G,H,I,J,K)
sheet P11-FPGA Pwr/Gnd
C65  1.0uF  [0402]
C66  0.1uF  [0402]
C67  10 nF  [4002]
C68  0.1uF  [0402]
C69  100uF  [1206]
C70  10uF  [0402]
C71  10uF  [0402]
C72  0.47uF  [0402]
C73  0.47uF  [0402]
C74  0.47uF  [0402]
C75  47nF  [0402]
C76  47nF  [0402]
C77  47nF  [0402]
C78  0.1uF  [0402]
C79  0.1uF  [0402]
C80  0.1uF  [0402]
C81  0.022uF  [0402]
C82  0.022uF  [0402]
C83  0.022uF  [0402]
C84  0.022uF  [0402]
C85  0.022uF  [0402]
C86  0.022uF  [0402]
C87  1.0uF  [0402]
C88  0.1uF  [0402]
C89  10 nF  [4002]
C90  10 nF  [0402]
C91  10 nF  [0402]
C92  10 nF  [0402]
C93  10 nF  [0402]
C94  10 nF  [0402]
C95  10 nF  [0402]
C96  4.7nF  [0402]
C97  4.7nF  [0402]
C98  4.7nF  [0402]
C99  4.7nF  [0402]
C100  4.7nF  [0402]
C101  4.7nF  [0402]
C102  4.7nF  [0402]
C103  4.7nF  [0402]
C104  10uF  [0603]
C105  10uF  [0603]
C106  0.1uF  [0402]
C107  0.1uF  [0402]
C108  0.1uF  [0402]
C109  0.1uF  [0402]
C110  0.1uF  [0402]
C111  0.1uF  [0402]
C112  0.1uF  [0402]
C113  0.1uF  [0402]
C114  0.1uF  [0402]
C115  0.1uF  [0402]
C116  10 nF  [0402]
C117  10 nF  [0402]
C118  10 nF  [0402]
C119  10 nF  [0402]
C120  10 nF  [0402]
C121  10 nF  [0402]
C122  10 nF  [0402]
C123  10 nF  [0402]
C124  10 nF  [0402]
C125  10 nF  [0402]
R56  2k  [0402]
sheet P12-Master Vid DMD DAD io
C126  15pF  [0402]
C127  15pF  [0402]
C128  15pF  [0402]
C129  15pF  [0402]
C130  15pF  [0402]
C131  15pF  [0402]
C132  15pF  [0402]
C133  15pF  [0402]
C134  15pF  [0402]
C135  15pF  [0402]
C136  15pF  [0402]
R57  4.7k  [0402]
R58  10  [0402]
R59  10  [0402]
R60  10  [0402]
R61  10  [0402]
R62  10  [0402]
R63  10  [0402]
R64  10  [0402]
R65  10  [0402]
R66  10  [0402]
R67  10  [0402]
R68  10  [0402]
TP13  Testpoint  [24mil-plated]
TP14  Testpoint  [24mil-plated]
TP15  Testpoint  [24mil-plated]
sheet P13-Master USB Osc Rst SSP
C137  0.1uF  [0402]
J6  TSM-102-01-T-SV  [2POS-2p54mm]
J7  TMMH-103-01-L-DV  [6POS-2ROWS-2mm]
J8  USB Type B Rcpt  [4thruhole]
R69  33  [0402]
R70  10k  [0402]
R71  10k  [0402]
R72  4.7k  [0402]
R73  4.7k  [0402]
R74  4.7k  [0402]
R75  4.7k  [0402]
R76  1k  [0402]
R77  33  [0402]
R78  33  [0402]
R79  33  [0402]
R80  33  [0402]
R81  33  [0402]
R82  10k  [0603]
R83  4.7K  [0402]
R84  1.5K  [0603]
R85  22  [2010]
R86  22  [2010]
TP16  Testpoint  [24mil-plated]
TP17  Testpoint  [24mil-plated]
U14  SN74AHC1G125DBVR  [SOT235]
U15  SN65220DBVT  [SOT23-6]
sheet P14-Master Ext Flash Intf
C138  0.1uF  [0402]
C139  0.1uF  [0402]
C367  0.1uF  [0402]
C368  0.1uF  [0402]
C378  0.1uF  [0402]
C379  0.1uF  [0402]
R89  10k  [0402]
R91  22  [0402]
R92  10k  [0402]
R93  10k  [0402]
R94  10k  [0402]
R95  10k  [0402]
R252  10k  [0402]
R253  10k  [0402]
R254  10k  [0402]
R260  10k  [0402]
R261  10k  [0402]
U13  DLPC900 (master)  [516BGA]  (sections A,B,C,D,E,F,G,H,I,J)
U43  S70GL02GS12FHIV10  [BGA64-BGA_NUMONYX]
U44  SN74ALVC08  [SOIC14-D_TI]
U45  SN74AUP1G14  [SOIC5-DCK_TI]
U50  SN74LVC1G11DBVR  [SOIC6-DBV_TI]

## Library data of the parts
PCB1 = DLP028_0: Board Instance; MFG: Any; MFG Part Number: DLP043; Part Number: DLP043
Z_MECH2 = PCB: Boot_Hold Shunt; MFG: Würth Elektronik; Notes: Kitting item; Part Number: 60900213421
C8 C9 = CER_18PF_50V_5%_NP0_0402
C10 = CER_1000PF_25V_10%_X7R_0402: MFG: Samsung; MFG Part Number: CL05B102KA5NNWC
C11 C14 = CER_0.1UF_25V_10%_X5R_0402
C12 C13 C16-C20 C22-C24 C26-C29 C31-C36 C38-C41 C43-C45 C47 C48 C50-C52 C54-C56 C58 C59 C61 C63 C66 C68 C78-C80 C88 C106-C115 C137-C139 C367 C368 C378 C379 = CER_0.1UF_16V_10%_X5R_0402: MFG: Samsung; MFG Part Number: CL05A104KO5NNNC
J4 J6 = TSM-102-01-T-SV_2POS_.1_SMD
R14 = 1M_OHM_1_10W_5%_0402
R15 R16 R32 = 0.0_OHM_1_10W_0402
R17 R21 R29 R30 R70 R71 R89 R92-R95 R252-R254 R260 R261 = 10K_OHM_1_10W_5%_0402
R18 R84 = 1.5K_OHM_1_10W_5%_0603
R19 R20 R24 R57 R72-R75 R83 = 4.7K_OHM_1_10W_5%_0402
R22 = 500_OHM_0.15W_0.05%_0603
R23 = 3K_OHM_1_16W_5%_0402
R25-R27 R33 R34 R91 = 22_OHM_1_10W_1%_0402
R28 R76 = 1.0K_OHM_1_16W_5%_0402
R31 = 100K_OHM_1_10W_1%_0603
RP1-RP15 = 22_OHM_ARR_1_32W_5%_0804
TP2-TP10 TP13-TP17 = Testpoint
U9 = M24C08L_dsize
U10 = IC_DUAL_FET_BUS_SWITCH_8-TSSOP
X1 = CRYSTAL_27MHZ_18PF_SMD
C15 C30 = CER_22UF_16V_10%_X5R_0805
C21 C25 C37 C49 C104 C105 = CER_10UF_16V_20%_X5R_0603
C42 C46 C53 C57 = CER_10UF_10V_20%_X5R_0603
C60 C62 C65 C87 = CER_1.0UF_16V_10%_X5R_0402: MFG: KEMET; MFG Part Number: C0402C105M4PAC7867
FB2-FB10 = FERRITE_BEAD_220_OHM_1A_0402
U8 = IT6535: Color: Default; Location X-Coordinate: 0; Location Y-Coordinate: 0; Power Pins Visible: False; Primitive: DEFAULT
U11 = FPGA_Cyclone5_5CEFA2F23C8N
C67 C89-C95 C116-C125 = CER_10_nF_25V_10%_X5R_0402: MFG: Samsung; MFG Part Number: CL05B103KA5NNNC
C69 = CER_100UF_6.3V_20%_X5R_1206
C70 C71 = CER_10UF_6.3V_20%_X5R_0402
C72-C74 = CER_0.47UF_10V_10%_X5R_0402
C75-C77 = CER_0.047UF_16V_10%_X7R_0402
C81-C86 = CER_0.022UF_10V_10%_X5R_0402
C96-C103 = CER_4.7nF_10V_10%_0402
R56 = 2K_OHM_1_10W_1%_0402
C126-C136 = CER_15PF_16V_5%_NP0_0402
R58-R68 = 10.0_OHM_1_16W_1%_0402
J7 = TMMH-103-01-L-DV_6POS_2ROWS_2MM
J8 = USB_RCPT_B-TYPE_R_A
R69 R77-R81 = 33_OHM_1_16W_5%_0402
R82 = 10K_OHM_1_10W_5%_0603
R85 R86 = 22.0_OHM_3_4W_1%_2010
U14 = 74AHC1G125
U15 = SN65220_USB_PORT_TVS
U13 = DLPC900_910_datasheet
U43 = 256MByteParallelFlash: MFG: Cypress
U44 = Quad2inAND: MFG: Texas Instruments; MFG Part Number: SN74ALVC08DR; PART NUMBER: SN74ALVC08DR
U45 = SN74AUP1G14: MFG: Texas Instruments; MFG Part Number: SN74AUP1G14DCKR; PART NUMBER: SN74AUP1G14DCKR
U50 = Single3inAND: MFG: Texas Instruments

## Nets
GND: C8.1 C9.1 C10.2 C11.2 C14.2 C15.2 C16.2 C17.2 C18.2 C19.2 C20.2 C21.2 C22.2 C23.2 C24.2 C25.2 C26.2 C27.2 C28.2 C29.2 C30.2 C31.2 C32.2 C33.2 C34.2 C35.2 C36.2 C37.2 C38.2 C39.2 C40.2 C41.2 C42.2 C43.2 C44.2 C45.2 C46.2 C47.2 C48.2 C49.2 C50.2 C51.2 C52.2 C53.2 C54.2 C55.2 C56.2 C57.2 C58.2 C59.2 C60.2 C61.2 C62.2 C63.2 C65.2 C66.2 C67.2 C68.2 C69.2 C70.2 C71.2 C72.2 C73.2 C74.2 C75.2 C76.2 C77.2 C78.2 C79.2 C80.2 C81.2 C82.2 C83.2 C84.2 C85.2 C86.2 C87.2 C88.2 C89.2 C90.2 C91.2 C92.2 C93.2 C94.2 C95.2 C96.2 C97.2 C98.2 C99.2 C100.2 C101.2 C102.2 C103.2 C104.2 C105.2 C106.2 C107.2 C108.2 C109.2 C110.2 C111.2 C112.2 C113.2 C114.2 C115.2 C116.2 C117.2 C118.2 C119.2 C120.2 C121.2 C122.2 C123.2 C124.2 C125.2 C126.2 C127.2 C128.2 C129.2 C130.2 C131.2 C132.2 C133.2 C134.2 C135.2 C136.2 C137.2 C138.2 C139.2 C367.2 C368.2 C378.2 C379.2 J4.2 J6.2 J7.6 J8.4 R20.2 R21.2 R22.2 R23.2 R24.2 R31.2 R56.2 R71.2 R82.2 R252.2 R253.2 R254.2 R260.2 R261.2 U8.2(OVSS) U8.12(IVSS) U8.21(OVSS) U8.37(IVSS) U8.39(OVSS) U8.68(OVSS) U8.71(IVSS) U8.72(IVSS) U8.87(AVSS) U8.92(AVSS) U8.95(AVSS) U8.99(AVSS) U8.105(PVSS) U8.107(IVSS) U8.110(PGND) U8.113(DVSS18) U8.117(AGND) U8.123(AGND) U8.127(DVSS18) U8.130(PGND) U8.148(OVSS) U8.150(IVSS) U8.163(OVSS) U9.1(E0) U9.2(E1) U9.3(E2) U9.4(VSS) U10.4(GND) U11.A11(GND) U11.A21(GND) U11.AA3(GND) U11.AA4(GND) U11.AA6(GND) U11.AA11(GND) U11.AB1(GND) U11.AB2(GND) U11.AB9(GND) U11.AB14(GND) U11.AB19(GND) U11.B1(GND) U11.B2(GND) U11.B9(GND) U11.B14(GND) U11.C3(GND) U11.C4(GND) U11.C17(GND) U11.D1(GND) U11.D2(GND) U11.D5(GND) U11.D10(GND) U11.D20(GND) U11.E3(GND) U11.E4(GND) U11.E13(GND) U11.F1(GND) U11.F2(GND) U11.F5(GND) U11.F6(GND) U11.F16(GND) U11.G3(GND) U11.G4(GND) U11.G9(GND) U11.G19(GND) U11.H1(GND) U11.H2(GND) U11.H3(GND) U11.H4(GND) U11.H7(GND) U11.H12(GND) U11.H22(GND) U11.J3(GND) U11.J5(GND) U11.J15(GND) U11.J20(GND) U11.K1(GND) U11.K2(GND) U11.K4(GND) U11.K8(GND) U11.K10(GND) U11.K12(GND) U11.K14(GND) U11.L3(GND) U11.L5(GND) U11.L11(GND) U11.L13(GND) U11.L15(GND) U11.L21(GND) U11.M1(GND) U11.M2(GND) U11.M4(GND) U11.M10(GND) U11.M12(GND) U11.M14(GND) U11.N3(GND) U11.N5(GND) U11.N7(GND) U11.N11(GND) U11.N13(GND) U11.N15(GND) U11.N17(GND) U11.N22(GND) U11.P1(GND) U11.P2(GND) U11.P4(GND) U11.P10(GND) U11.R3(GND) U11.R13(GND) U11.T1(GND) U11.T2(GND) U11.T16(GND) U11.T21(GND) U11.U3(GND) U11.U4(GND) U11.U5(GND) U11.U9(GND) U11.V1(GND) U11.V2(GND) U11.V4(GND) U11.V7(GND) U11.V12(GND) U11.V17(GND) U11.V22(GND) U11.W3(GND) U11.W4(GND) U11.Y1(GND) U11.Y2(GND) U11.Y5(GND) U11.Y18(GND) U14.3(GND) U15.2(GND2) U15.5(GND5) U43.E8(VSS) U43.H2(VSS) U43.H7(VSS) U44.7(GND) U45.3(GND) U50.2(GND) ; also on sheet 1 3 4 5 7 8 9 10 11 13 14 15 16 27 28 29
AFE_ARSTZ: R57.2 U8.74(SYSRSTN) U13.AC12(AFE_ARSTZ) ; also on sheet 1 5
DA_B0: RP8.7 ; also on sheet 1 6
DA_B1: RP8.8 ; also on sheet 1 6
DA_B2: RP7.5 ; also on sheet 1 6
DA_B3: RP7.6 ; also on sheet 1 6
DA_B4: RP7.7 ; also on sheet 1 6
DA_B5: RP7.8 ; also on sheet 1 6
DA_B6: RP6.5 ; also on sheet 1 6
DA_B7: RP6.6 ; also on sheet 1 6
DA_B8: RP6.7 ; also on sheet 1 6
DA_B9: RP6.8 ; also on sheet 1 6
DA_G0: RP5.5 ; also on sheet 1 6
DA_G1: RP5.6 ; also on sheet 1 6
DA_G2: RP5.7 ; also on sheet 1 6
DA_G3: RP5.8 ; also on sheet 1 6
DA_G4: RP4.5 ; also on sheet 1 6
DA_G5: RP4.6 ; also on sheet 1 6
DA_G6: RP4.7 ; also on sheet 1 6
DA_G7: RP4.8 ; also on sheet 1 6
DA_G8: RP3.5 ; also on sheet 1 6
DA_G9: RP3.6 ; also on sheet 1 6
DA_R0: RP3.7 ; also on sheet 1 6
DA_R1: RP3.8 ; also on sheet 1 6
DA_R2: RP2.5 ; also on sheet 1 6
DA_R3: RP2.6 ; also on sheet 1 6
DA_R4: RP2.7 ; also on sheet 1 6
DA_R5: RP2.8 ; also on sheet 1 6
DA_R6: RP1.5 ; also on sheet 1 6
DA_R7: RP1.6 ; also on sheet 1 6
DA_R8: RP1.7 ; also on sheet 1 6
DA_R9: RP1.8 ; also on sheet 1 6
DADADDR0: R58.2 ; also on sheet 8
DADADDR1: R59.2 ; also on sheet 8
DADADDR2: R60.2 ; also on sheet 8
DADADDR3: R61.2 ; also on sheet 8
DADIRQZ: R68.2 ; also on sheet 8
DADMODE0: R62.2 ; also on sheet 8
DADMODE1: R63.2 ; also on sheet 8
DADOEZ: R67.2 ; also on sheet 8
DADSEL0: R64.2 ; also on sheet 8
DADSEL1: R65.2 ; also on sheet 8
DADSTRB: R66.2 TP15.1 ; also on sheet 8
DB_B0: R34.2 ; also on sheet 1 6
DB_B1: R33.2 ; also on sheet 1 6
DB_B2: RP15.5 ; also on sheet 1 6
DB_B3: RP15.6 ; also on sheet 1 6
DB_B4: RP15.7 ; also on sheet 1 6
DB_B5: RP15.8 ; also on sheet 1 6
DB_B6: RP14.5 ; also on sheet 1 6
DB_B7: RP14.6 ; also on sheet 1 6
DB_B8: RP14.7 ; also on sheet 1 6
DB_B9: RP14.8 ; also on sheet 1 6
DB_G0: RP13.5 ; also on sheet 1 6
DB_G1: RP13.6 ; also on sheet 1 6
DB_G2: RP13.7 ; also on sheet 1 6
DB_G3: RP13.8 ; also on sheet 1 6
DB_G4: RP12.5 ; also on sheet 1 6
DB_G5: RP12.6 ; also on sheet 1 6
DB_G6: RP12.7 ; also on sheet 1 6
DB_G7: RP12.8 ; also on sheet 1 6
DB_G8: RP11.5 ; also on sheet 1 6
DB_G9: RP11.6 ; also on sheet 1 6
DB_R0: RP11.7 ; also on sheet 1 6
DB_R1: RP11.8 ; also on sheet 1 6
DB_R2: RP10.5 ; also on sheet 1 6
DB_R3: RP10.6 ; also on sheet 1 6
DB_R4: RP10.7 ; also on sheet 1 6
DB_R5: RP10.8 ; also on sheet 1 6
DB_R6: RP9.5 ; also on sheet 1 6
DB_R7: RP9.6 ; also on sheet 1 6
DB_R8: RP9.7 ; also on sheet 1 6
DB_R9: RP9.8 ; also on sheet 1 6
DP_DDCSCL: R29.2 U8.79(DDCSCL) U9.6(SCL) U10.2(1A)
DP_DDCSDA: R30.2 U8.80(DDCSDA) U9.5(SDA) U10.5(2A)
DP_EDID_WE: J4.1 R28.2 R32.1 U9.7(WC/)
DP_RXAUXN: C13.1 U8.108(RXAUXN)
DP_RXAUXP: C12.1 U8.109(RXAUXP)
DPIICWR_OEZ: R32.2 U10.1(1~{OE}) U10.7(2~{OE})
DRX_AUXN: C13.2 U8.82(DCAUXN) ; also on sheet 29
DRX_AUXP: C12.2 U8.83(DCAUXP) ; also on sheet 29
DRX_HPD: R31.1 TP10.1 U8.81(HPD) ; also on sheet 29
DRX_LN0N: U8.116(DRX0N) ; also on sheet 29
DRX_LN0P: U8.115(DRX0P) ; also on sheet 29
DRX_LN1N: U8.119(DRX1N) ; also on sheet 29
DRX_LN1P: U8.118(DRX1P) ; also on sheet 29
DRX_LN2N: U8.122(DRX2N) ; also on sheet 29
DRX_LN2P: U8.121(DRX2P) ; also on sheet 29
DRX_LN3N: U8.125(DRX3N) ; also on sheet 29
DRX_LN3P: U8.124(DRX3P) ; also on sheet 29
F_RREF_TL: R56.1 U11.A1(RREF_TL)
F_VCCIO: C68.1 C104.1 C105.1 C106.1 C107.1 C108.1 C109.1 C110.1 C111.1 C112.1 C113.1 C114.1 C115.1 C116.1 C117.1 C118.1 C119.1 C120.1 C121.1 C122.1 C123.1 C124.1 C125.1 U11.A3(VCCBAT) U11.C10(VCCPD7A8A) U11.D8(VCCPD7A8A) U11.D14(VCCPD7A8A) U11.D16(VCCPD7A8A) U11.E1(VCCPD1A2A) U11.E11(VCCPD7A8A) U11.F8(VCCPGM) U11.J2(VCCPD1A2A) U11.R2(VCCPD1A2A) U11.R19(VCCPGM) U11.V8(VCCPGM) U11.W11(VCCPD3B4A) U11.W12(VCCPD3B4A) U11.W14(VCCPD3B4A) U11.W17(VCCPD3B4A) ; also on sheet 3 4 5 6
HDMI_5V: R18.1 ; also on sheet 29
HDMI_CEC: U13.G23(RESERVED) ; also on sheet 1
HDMI_INTZ: R17.1 TP9.1 U8.75(INT#) U13.AB13(AFE_IRQ) ; also on sheet 1
HRX_CKN: U8.90(HRXCM) ; also on sheet 29
HRX_CKP: U8.91(HRXCP) ; also on sheet 29
HRX_D0N: U8.93(HRX0M) ; also on sheet 29
HRX_D0P: U8.94(HRX0P) ; also on sheet 29
HRX_D1N: U8.97(HRX1M) ; also on sheet 29
HRX_D1P: U8.98(HRX1P) ; also on sheet 29
HRX_D2N: U8.101(HRX2M) ; also on sheet 29
HRX_D2P: U8.102(HRX2P) ; also on sheet 29
HRX_DDCCLK: R15.1 ; also on sheet 29
HRX_DDCDAT: R16.1 ; also on sheet 29
HRXDDCSCL: R15.2 U8.85(RXDDCSCL)
HRXDDCSDA: R16.2 U8.84(RXDDCSDA)
IT_DE_PIN: R26.1 U8.5(DE)
IT_EMEMVPP: R21.1 U8.49(EMEM_VPP)
IT_ENTEST: R20.1 U8.73(ENTEST)
IT_FIELD_PIN: R25.1 U8.3(FIELD)
IT_HS_PIN: RP8.3 U8.7(HSYNC)
IT_PCADR: R19.2 R24.1 U8.76(PCADR)
IT_PCLK: R27.1 U8.4(PCLK)
IT_PWR5V: C10.1 R18.2 R23.1 U8.86(PWR5V)
IT_REXT: R22.1 U8.103(REXT)
IT_VS_PIN: RP8.4 U8.6(VSYNC)
IT_XTALIN: C8.2 R14.1 U8.132(XTALIN) X1.3
IT_XTALOUT: C9.2 R14.2 U8.131(XTALOUT) X1.1
ITE_ASPVCC: C60.1 C61.1 FB9.2 U8.133(ASPVCC)
ITE_AVCC: C42.1 C43.1 C44.1 C45.1 FB4.2 U8.114(AVCC_1P8) U8.120(AVCC_1P8) U8.126(AVCC_1P8)
ITE_AVCC18: C53.1 C54.1 C55.1 C56.1 FB7.2 U8.88(AVCC18)
ITE_AVCC33: C49.1 C50.1 C51.1 C52.1 FB6.2 U8.89(AVCC33) U8.96(AVCC33) U8.100(AVCC33)
ITE_DE: R26.2 ; also on sheet 1 6
ITE_DVDD1P8: C46.1 C47.1 C48.1 FB5.2 U8.112(DVDD18) U8.128(DVDD18)
ITE_FIELD: R25.2 ; also on sheet 1 6
ITE_HS: RP8.6 ; also on sheet 1 6
ITE_IVDD1P8: C30.1 C31.1 C32.1 C33.1 C34.1 C35.1 C36.1 FB3.2 U8.11(IVDD_1P8) U8.36(IVDD_1P8) U8.69(IVDD_1P8) U8.70(IVDD_1P8) U8.106(IVDD_1P8) U8.149(IVDD_1P8)
ITE_OVDD3P3: C15.1 C16.1 C17.1 C18.1 C19.1 C20.1 C23.1 FB2.2 U8.1(OVDD_3P3) U8.20(OVDD_3P3) U8.38(OVDD_3P3) U8.67(OVDD_3P3) U8.147(OVDD_3P3) U8.162(OVDD_3P3)
ITE_PVCC: C57.1 C58.1 C59.1 FB8.2 U8.111(PVCC) U8.129(PVCC)
ITE_PVCC18: C62.1 C63.1 FB10.2 U8.104(PVCC18)
ITE_VS: RP8.5 ; also on sheet 1 6
M_3DLR_GPIO78: U13.AF9(RESERVED) ; also on sheet 5
M_CW_PWM: TP16.1 U13.AD8(RESERVED)
M_DADA0: C129.1 R58.1 U13.AB8(DADADDR_0)
M_DADA1: C128.1 R59.1 U13.AF4(DADADDR_1)
M_DADA2: C127.1 R60.1 U13.AE5(DADADDR_2)
M_DADA3: C126.1 R61.1 U13.AD6(DADADDR_3)
M_DADINTZ: C130.1 R68.1 U13.AC8(DAD_INTZ)
M_DADM0: C136.1 R62.1 U13.AE6(DADMODE_0)
M_DADM1: C135.1 R63.1 U13.AD7(DADMODE_1)
M_DADOEZ: C131.1 R67.1 U13.AE7(DADOEZ)
M_DADSEL0: C134.1 R64.1 U13.AC7(DADSEL_0)
M_DADSEL1: C133.1 R65.1 U13.AE4(DADSEL_1)
M_DADSTB: C132.1 R66.1 U13.AF5(DADSTRB)
M_DCLKA_N: U13.J4(DCKB_N) ; also on sheet 8
M_DCLKA_P: U13.J3(DCKB_P) ; also on sheet 8
M_DCLKB_N: U13.V3(DCKA_N) ; also on sheet 8
M_DCLKB_P: U13.V4(DCKA_P) ; also on sheet 8
M_DDA00_N: U13.N2(DDB_N_15) ; also on sheet 8
M_DDA00_P: U13.N1(DDB_P_15) ; also on sheet 8
M_DDA01_N: U13.N4(DDB_N_14) ; also on sheet 8
M_DDA01_P: U13.N3(DDB_P_14) ; also on sheet 8
M_DDA02_N: U13.M1(DDB_N_13) ; also on sheet 8
M_DDA02_P: U13.M2(DDB_P_13) ; also on sheet 8
M_DDA03_N: U13.M4(DDB_N_12) ; also on sheet 8
M_DDA03_P: U13.M3(DDB_P_12) ; also on sheet 8
M_DDA04_N: U13.L2(DDB_N_11) ; also on sheet 8
M_DDA04_P: U13.L1(DDB_P_11) ; also on sheet 8
M_DDA05_N: U13.L4(DDB_N_10) ; also on sheet 8
M_DDA05_P: U13.L3(DDB_P_10) ; also on sheet 8
M_DDA06_N: U13.K2(DDB_N_9) ; also on sheet 8
M_DDA06_P: U13.K1(DDB_P_9) ; also on sheet 8
M_DDA07_N: U13.K4(DDB_N_8) ; also on sheet 8
M_DDA07_P: U13.K3(DDB_P_8) ; also on sheet 8
M_DDA08_N: U13.H2(DDB_N_7) ; also on sheet 8
M_DDA08_P: U13.H1(DDB_P_7) ; also on sheet 8
M_DDA09_N: U13.H4(DDB_N_6) ; also on sheet 8
M_DDA09_P: U13.H3(DDB_P_6) ; also on sheet 8
M_DDA10_N: U13.G2(DDB_N_5) ; also on sheet 8
M_DDA10_P: U13.G1(DDB_P_5) ; also on sheet 8
M_DDA11_N: U13.G4(DDB_N_4) ; also on sheet 8
M_DDA11_P: U13.G3(DDB_P_4) ; also on sheet 8
M_DDA12_N: U13.F2(DDB_N_3) ; also on sheet 8
M_DDA12_P: U13.F1(DDB_P_3) ; also on sheet 8
M_DDA13_N: U13.F4(DDB_N_2) ; also on sheet 8
M_DDA13_P: U13.F3(DDB_P_2) ; also on sheet 8
M_DDA14_N: U13.E2(DDB_N_1) ; also on sheet 8
M_DDA14_P: U13.E1(DDB_P_1) ; also on sheet 8
M_DDA15_N: U13.D2(DDB_N_0) ; also on sheet 8
M_DDA15_P: U13.D1(DDB_P_0) ; also on sheet 8
M_DDB00_N: U13.P3(DDA_N_15) ; also on sheet 8
M_DDB00_P: U13.P4(DDA_P_15) ; also on sheet 8
M_DDB01_N: U13.P1(DDA_N_14) ; also on sheet 8
M_DDB01_P: U13.P2(DDA_P_14) ; also on sheet 8
M_DDB02_N: U13.R3(DDA_N_13) ; also on sheet 8
M_DDB02_P: U13.R4(DDA_P_13) ; also on sheet 8
M_DDB03_N: U13.R1(DDA_N_12) ; also on sheet 8
M_DDB03_P: U13.R2(DDA_P_12) ; also on sheet 8
M_DDB04_N: U13.T3(DDA_N_11) ; also on sheet 8
M_DDB04_P: U13.T4(DDA_P_11) ; also on sheet 8
M_DDB05_N: U13.T1(DDA_N_10) ; also on sheet 8
M_DDB05_P: U13.T2(DDA_P_10) ; also on sheet 8
M_DDB06_N: U13.U3(DDA_N_9) ; also on sheet 8
M_DDB06_P: U13.U4(DDA_P_9) ; also on sheet 8
M_DDB07_N: U13.U1(DDA_N_8) ; also on sheet 8
M_DDB07_P: U13.U2(DDA_P_8) ; also on sheet 8
M_DDB08_N: U13.W3(DDA_N_7) ; also on sheet 8
M_DDB08_P: U13.W4(DDA_P_7) ; also on sheet 8
M_DDB09_N: U13.W1(DDA_N_6) ; also on sheet 8
M_DDB09_P: U13.W2(DDA_P_6) ; also on sheet 8
M_DDB10_N: U13.Y1(DDA_N_5) ; also on sheet 8
M_DDB10_P: U13.Y2(DDA_P_5) ; also on sheet 8
M_DDB11_N: U13.Y3(DDA_N_4) ; also on sheet 8
M_DDB11_P: U13.Y4(DDA_P_4) ; also on sheet 8
M_DDB12_N: U13.AA1(DDA_N_3) ; also on sheet 8
M_DDB12_P: U13.AA2(DDA_P_3) ; also on sheet 8
M_DDB13_N: U13.AA3(DDA_N_2) ; also on sheet 8
M_DDB13_P: U13.AA4(DDA_P_2) ; also on sheet 8
M_DDB14_N: U13.AB1(DDA_N_1) ; also on sheet 8
M_DDB14_P: U13.AB2(DDA_P_1) ; also on sheet 8
M_DDB15_N: U13.AC1(DDA_N_0) ; also on sheet 8
M_DDB15_P: U13.AC2(DDA_P_0) ; also on sheet 8
M_EXT_RSTZ: R72.1 U13.T24(EXT_RSTZ) ; also on sheet 8
M_FLASH0_WP#: R89.2 U43.B4(WP#)
M_OCLKA_PIN: R69.1 U13.AF6(OCLKA)
M_OSC20M: U13.M26(MOSCP) ; also on sheet 14
M_P1A0: U13.AE12(P1_A0) ; also on sheet 5
M_P1A1: U13.AF12(P1_A1) ; also on sheet 5
M_P1A2: U13.AF13(P1_A2) ; also on sheet 5
M_P1A3: U13.AF14(P1_A3) ; also on sheet 5
M_P1A4: U13.AC13(P1_A4) ; also on sheet 5
M_P1A5: U13.AD13(P1_A5) ; also on sheet 5
M_P1A6: U13.AE13(P1_A6) ; also on sheet 5
M_P1A7: U13.AE14(P1_A7) ; also on sheet 5
M_P1A8: U13.AE15(P1_A8) ; also on sheet 5
M_P1A9: U13.AD15(P1_A9) ; also on sheet 5
M_P1B0: U13.AD14(P1_B0) ; also on sheet 5
M_P1B1: U13.AC14(P1_B1) ; also on sheet 5
M_P1B2: U13.AF15(P1_B2) ; also on sheet 5
M_P1B3: U13.AF16(P1_B3) ; also on sheet 5
M_P1B4: U13.AE16(P1_B4) ; also on sheet 5
M_P1B5: U13.AD16(P1_B5) ; also on sheet 5
M_P1B6: U13.AC16(P1_B6) ; also on sheet 5
M_P1B7: U13.AC15(P1_B7) ; also on sheet 5
M_P1B8: U13.AB18(P1_B8) ; also on sheet 5
M_P1B9: U13.AF18(P1_B9) ; also on sheet 5
M_P1C0: U13.AE18(P1_C0) ; also on sheet 5
M_P1C1: U13.AC19(P1_C1) ; also on sheet 5
M_P1C2: U13.AF20(P1_C2) ; also on sheet 5
M_P1C3: U13.AF19(P1_C3) ; also on sheet 5
M_P1C4: U13.AE19(P1_C4) ; also on sheet 5
M_P1C5: U13.AD19(P1_C5) ; also on sheet 5
M_P1C6: U13.AF21(P1_C6) ; also on sheet 5
M_P1C7: U13.AE21(P1_C7) ; also on sheet 5
M_P1C8: U13.AE20(P1_C8) ; also on sheet 5
M_P1C9: U13.AD20(P1_C9) ; also on sheet 5
M_P1DATEN: TP13.1 U13.AF22(P_DATAEN1) ; also on sheet 5
M_P1HS: U13.AD21(P1_HSYNC) ; also on sheet 5
M_P1VS: TP14.1 U13.AC20(P1_VSYNC) ; also on sheet 5
M_P2A0: U13.AB19(P2_A0) ; also on sheet 5
M_P2A1: U13.AE23(P2_A1) ; also on sheet 5
M_P2A2: U13.AD22(P2_A2) ; also on sheet 5
M_P2A3: U13.AC21(P2_A3) ; also on sheet 5
M_P2A4: U13.AB20(P2_A4) ; also on sheet 5
M_P2A5: U13.AD23(P2_A5) ; also on sheet 5
M_P2A6: U13.AC22(P2_A6) ; also on sheet 5
M_P2A7: U13.AB21(P2_A7) ; also on sheet 5
M_P2A8: U13.AD25(P2_A8) ; also on sheet 5
M_P2A9: U13.AD26(P2_A9) ; also on sheet 5
M_P2B0: U13.AC24(P2_B0) ; also on sheet 5
M_P2B1: U13.AC25(P2_B1) ; also on sheet 5
M_P2B2: U13.AB23(P2_B2) ; also on sheet 5
M_P2B3: U13.AC26(P2_B3) ; also on sheet 5
M_P2B4: U13.AB24(P2_B4) ; also on sheet 5
M_P2B5: U13.AA22(P2_B5) ; also on sheet 5
M_P2B6: U13.AB25(P2_B6) ; also on sheet 5
M_P2B7: U13.AA23(P2_B7) ; also on sheet 5
M_P2B8: U13.AB26(P2_B8) ; also on sheet 5
M_P2B9: U13.Y22(P2_B9) ; also on sheet 5
M_P2C0: U13.AA24(P2_C0) ; also on sheet 5
M_P2C1: U13.AA25(P2_C1) ; also on sheet 5
M_P2C2: U13.AA26(P2_C2) ; also on sheet 5
M_P2C3: U13.W22(P2_C3) ; also on sheet 5
M_P2C4: U13.Y23(P2_C4) ; also on sheet 5
M_P2C5: U13.Y24(P2_C5) ; also on sheet 5
M_P2C6: U13.Y25(P2_C6) ; also on sheet 5
M_P2C7: U13.Y26(P2_C7) ; also on sheet 5
M_P2C8: U13.V22(P2_C8) ; also on sheet 5
M_P2C9: U13.W23(P2_C9) ; also on sheet 5
M_PCLK1: U13.AE22(P_CLK1) ; also on sheet 5
M_PM_ADDR_GPIO45: R254.1 U13.U23(GPIO_45_PM_ADDR) U44.5(2B)
M_PM_ADDR_GPIO46: R253.1 U13.T22(GPIO_46_PM_ADDR) U44.2(1B)
M_PM_ADDR_GPIO60: R252.1 U13.H22(GPIO_60_PM_ADDR) U44.9(3A)
M_PM_CEZ: U43.F2(CE#) U50.4(Y)
M_PM_CSZ0: R94.2 U13.D13(PM_CSZ_0) U50.1(A)
M_PM_CSZ1: R93.2 U13.E12(PM_CSZ_1) U44.1(1A) U44.4(2A) U44.10(3B) U50.3(B)
M_PM_CSZ2: R92.2 U13.A13(PM_CSZ_2) U45.2(A) U50.6(C)
M_PM_OEZ: U13.C13(PM_OEZ) U43.G2(OE#)
M_PM_WEZ: R91.1 U43.A5(WE#)
M_PMADDR00: U13.C7(PM_ADDR_00) U43.E2(A0)
M_PMADDR01: U13.A7(PM_ADDR_01) U43.D2(A1)
M_PMADDR02: U13.B7(PM_ADDR_02) U43.C2(A2)
M_PMADDR03: U13.C8(PM_ADDR_03) U43.A2(A3)
M_PMADDR04: U13.D8(PM_ADDR_04) U43.B2(A4)
M_PMADDR05: U13.A8(PM_ADDR_05) U43.D3(A5)
M_PMADDR06: U13.B8(PM_ADDR_06) U43.C3(A6)
M_PMADDR07: U13.C9(PM_ADDR_07) U43.A3(A7)
M_PMADDR08: U13.D9(PM_ADDR_08) U43.B6(A8)
M_PMADDR09: U13.E9(PM_ADDR_09) U43.A6(A9)
M_PMADDR10: U13.A9(PM_ADDR_10) U43.C6(A10)
M_PMADDR11: U13.B9(PM_ADDR_11) U43.D6(A11)
M_PMADDR12: U13.C10(PM_ADDR_12) U43.B7(A12)
M_PMADDR13: U13.D10(PM_ADDR_13) U43.A7(A13)
M_PMADDR14: U13.E10(PM_ADDR_14) U43.C7(A14)
M_PMADDR15: U13.C11(PM_ADDR_15) U43.D7(A15)
M_PMADDR16: U13.D11(PM_ADDR_16) U43.E7(A16)
M_PMADDR17: U13.A11(PM_ADDR_17) U43.B3(A17)
M_PMADDR18: U13.B11(PM_ADDR_18) U43.C4(A18)
M_PMADDR19: U13.C12(PM_ADDR_19) U43.D5(A19)
M_PMADDR20: U13.D12(PM_ADDR_20) U43.D4(A20)
M_PMADDR21: R260.1 U13.E11(PM_ADDR_21) U43.C5(A21)
M_PMADDR22: R261.1 U13.A12(PM_ADDR_22) U43.B8(A22)
M_PMADDR23: U43.C8(A23) U45.4(Y)
M_PMADDR24: U43.F8(A24) U44.6(2Y)
M_PMADDR25: U43.G8(A25) U44.3(1Y)
M_PMADDR26: U43.B1(A26) U44.8(3Y)
M_PMDATA_00: U13.B13(PM_DATA_00) U43.E3(DQ0)
M_PMDATA_01: U13.C14(PM_DATA_01) U43.H3(DQ1)
M_PMDATA_02: U13.D14(PM_DATA_02) U43.E4(DQ2)
M_PMDATA_03: U13.E13(PM_DATA_03) U43.H4(DQ3)
M_PMDATA_04: U13.A14(PM_DATA_04) U43.H5(DQ4)
M_PMDATA_05: U13.B14(PM_DATA_05) U43.E5(DQ5)
M_PMDATA_06: U13.C15(PM_DATA_06) U43.H6(DQ6)
M_PMDATA_07: U13.D15(PM_DATA_07) U43.E6(DQ7)
M_PMDATA_08: U13.E14(PM_DATA_08) U43.F3(DQ8)
M_PMDATA_09: U13.C16(PM_DATA_09) U43.G3(DQ9)
M_PMDATA_10: U13.D16(PM_DATA_10) U43.F4(DQ10)
M_PMDATA_11: U13.B15(PM_DATA_11) U43.G4(DQ11)
M_PMDATA_12: U13.A15(PM_DATA_12) U43.F5(DQ12)
M_PMDATA_13: U13.A16(PM_DATA_13) U43.G6(DQ13)
M_PMDATA_14: U13.B16(PM_DATA_14) U43.F6(DQ14)
M_PMDATA_15: U13.C17(PM_DATA_15) U43.G7(DQ15)
M_PMDINTZ: R70.2 U13.AE8(RESERVED)
M_PMWEZ_PIN: R91.2 U13.B12(PM_WEZ)
M_POSENSE: U13.P22(POSENSE) U43.B5(RESET#) ; also on sheet 14
M_SCL1: U8.77(PCSCL) U10.3(1B) ; also on sheet 1 10 15 29
M_SCTLA_N: U13.J2(SCB_N) ; also on sheet 8
M_SCTLA_P: U13.J1(SCB_P) ; also on sheet 8
M_SCTLB_N: U13.V1(SCA_N) ; also on sheet 8
M_SCTLB_P: U13.V2(SCA_P) ; also on sheet 8
M_SDA1: U8.78(PCSDA) U10.6(2B) ; also on sheet 1 10 15 29
M_SSP0_CLK: R77.1 U13.AD4(SSP0_CLK)
M_SSP0_CSZ0: R73.2 R81.1 U13.AC5(SSP0_CSZ_0)
M_SSP0_CSZ1: R74.2 R80.1 U13.AB6(SSP0_CSZ_1)
M_SSP0_CSZ2: R75.2 R79.1 U13.AC3(SSP0_CSZ_2)
M_SSP0_TXD: R78.1 U13.AB7(SSP0_TXD)
M_UART0_CTSZ: J7.4 R71.1 U13.AE2(UART0_CTSZ)
M_UART0_RTSZ: J7.5 U13.AD2(UART0_RTSZ)
M_UART0_RXD: J7.3 U13.AD1(UART0_RXD)
M_UART0_TXD: J7.2 U13.AB3(UART0_TXD)
M_USB_ENZ: R83.1 U14.1(~{OE}) ; also on sheet 15
M_USB_N: R85.2 U13.C5(USB_DAT_N)
M_USB_P: R86.2 U13.D6(USB_DAT_P)
MFLASH_RYBYZ: R95.2 U43.A4(RY/BY#)
OCLKA: J6.1 R69.2
P1P1V: C69.1 C70.1 C71.1 C72.1 C73.1 C74.1 C75.1 C76.1 C77.1 C78.1 C79.1 C80.1 C81.1 C82.1 C83.1 C84.1 C85.1 C86.1 C90.1 C91.1 C92.1 C93.1 C94.1 C95.1 C96.1 C97.1 C98.1 C99.1 C100.1 C101.1 C102.1 C103.1 U11.J4(VCC) U11.J10(VCC) U11.J12(VCC) U11.J14(VCC) U11.J16(VCC) U11.K3(VCC) U11.K5(VCC) U11.K11(VCC) U11.K13(VCC) U11.K15(VCC) U11.L4(VCC) U11.L10(VCC) U11.L12(VCC) U11.L14(VCC) U11.L16(VCC) U11.M11(VCC) U11.M13(VCC) U11.M15(VCC) U11.N4(VCC) U11.N10(VCC) U11.N12(VCC) U11.N14(VCC) U11.P3(VCC) U11.P11(VCC) U11.P13(VCC) U11.P15(VCC) ; also on sheet 7 27 28
P1P8V: C25.1 C26.1 C27.1 C28.1 C29.1 FB3.1 FB5.1 ; also on sheet 7 13 27 28
P1P8V_ITEA: C37.1 C38.1 C39.1 C40.1 C41.1 FB4.1 FB7.1 FB8.1 FB9.1 FB10.1 ; also on sheet 3
P2P5V_FAUXPLL: C65.1 C66.1 C67.1 C87.1 C88.1 C89.1 U11.D11(VCC_AUX) U11.D18(VCC_AUX) U11.E6(VCC_AUX) U11.F4(VCCA_FPLL) U11.H19(VCCA_FPLL) U11.M3(VCCA_FPLL) U11.T3(VCCA_FPLL) U11.T5(VCCA_FPLL) U11.U18(VCCA_FPLL) U11.W7(VCC_AUX) U11.W13(VCC_AUX) U11.W18(VCC_AUX) ; also on sheet 3
P3P3V: C11.1 C14.1 C21.1 C22.1 C24.1 C137.1 C138.1 C139.1 C367.1 C368.1 C378.1 C379.1 FB2.1 FB6.1 J7.1 R17.2 R19.1 R28.1 R29.1 R30.1 R57.1 R70.1 R72.2 R73.1 R74.1 R75.1 R76.1 R83.2 R89.1 R92.1 R93.1 R94.1 R95.1 U9.8(VCC) U10.8(VCC) U14.5(VCC) U43.D8(VIO) U43.F1(VIO) U43.G5(VCC) U44.14(VCC) U45.5(VCC) U50.5(VCC) ; also on sheet 3 4 7 8 9 10 11 12 13 14 15 16 27 28 29
PCLK: R27.2 ; also on sheet 1 6
POWERGOOD: U13.T26(PWRGOOD) ; also on sheet 14 16
QA_B0: RP8.2 U8.10(QA2)
QA_B1: RP8.1 U8.13(QA3)
QA_B2: RP7.4 U8.14(QA4)
QA_B3: RP7.3 U8.15(QA5)
QA_B4: RP7.2 U8.16(QA6)
QA_B5: RP7.1 U8.17(QA7)
QA_B6: RP6.4 U8.18(QA8)
QA_B7: RP6.3 U8.19(QA9)
QA_B8: RP6.2 U8.22(QA10)
QA_B9: RP6.1 U8.23(QA11)
QA_G0: RP5.4 U8.26(QA14)
QA_G1: RP5.3 U8.27(QA15)
QA_G2: RP5.2 U8.28(QA16)
QA_G3: RP5.1 U8.29(QA17)
QA_G4: RP4.4 U8.30(QA18)
QA_G5: RP4.3 U8.31(QA19)
QA_G6: RP4.2 U8.32(QA20)
QA_G7: RP4.1 U8.33(QA21)
QA_G8: RP3.4 U8.34(QA22)
QA_G9: RP3.3 U8.35(QA23)
QA_R0: RP3.2 U8.42(QA26)
QA_R1: RP3.1 U8.43(QA27)
QA_R2: RP2.4 U8.44(QA28)
QA_R3: RP2.3 U8.45(QA29)
QA_R4: RP2.2 U8.46(QA30)
QA_R5: RP2.1 U8.47(QA31)
QA_R6: RP1.4 U8.48(QA32)
QA_R7: RP1.3 U8.50(QA33)
QA_R8: RP1.2 U8.51(QA34)
QA_R9: RP1.1 U8.52(QA35)
QB_B0: R34.1 U8.141(QB2)
QB_B1: R33.1 U8.142(QB3)
QB_B2: RP15.4 U8.143(QB4)
QB_B3: RP15.3 U8.144(QB5)
QB_B4: RP15.2 U8.145(QB6)
QB_B5: RP15.1 U8.146(QB7)
QB_B6: RP14.4 U8.151(QB8)
QB_B7: RP14.3 U8.152(QB9)
QB_B8: RP14.2 U8.153(QB10)
QB_B9: RP14.1 U8.154(QB11)
QB_G0: RP13.4 U8.155(QB14)
QB_G1: RP13.3 U8.156(QB15)
QB_G2: RP13.2 U8.157(QB16)
QB_G3: RP13.1 U8.158(QB17)
QB_G4: RP12.4 U8.159(QB18)
QB_G5: RP12.3 U8.160(QB19)
QB_G6: RP12.2 U8.161(QB20)
QB_G7: RP12.1 U8.164(QB21)
QB_G8: RP11.4 U8.165(QB22)
QB_G9: RP11.3 U8.166(QB23)
QB_R0: RP11.2 U8.167(QB26)
QB_R1: RP11.1 U8.168(QB27)
QB_R2: RP10.4 U8.169(QB28)
QB_R3: RP10.3 U8.170(QB29)
QB_R4: RP10.2 U8.171(QB30)
QB_R5: RP10.1 U8.172(QB31)
QB_R6: RP9.4 U8.173(QB32)
QB_R7: RP9.3 U8.174(QB33)
QB_R8: RP9.2 U8.175(QB34)
QB_R9: RP9.1 U8.176(QB35)
SSP0_CLK: R77.2 ; also on sheet 6 8 11
SSP0_CSZ0_DAD1: R81.2 ; also on sheet 8
SSP0_CSZ1_DMD: R80.2 ; also on sheet 8
SSP0_CSZ2_FPGA: R79.2 ; also on sheet 6
SSP0_RXD_S2M: R76.2 U13.AD5(SSP0_RXD) ; also on sheet 6 8 11
SSP0_TXD_M2S: R78.2 ; also on sheet 6 8 11
SSP1_CLK: U13.D25(RESERVED) ; also on sheet 13
SSP1_CSZ_0: U13.D26(RESERVED) ; also on sheet 13
SSP1_CSZ_1: U13.F23(RESERVED) ; also on sheet 13
SSP1_DIN: U13.F22(RESERVED) ; also on sheet 13
SSP1_DO: U13.E24(RESERVED) ; also on sheet 13
TRIGGER_IN1: U13.AF7(TRIG_IN_1) ; also on sheet 11 13
USB_DAT_N: J8.2 R85.1 U15.3(NC3) U15.4(B)
USB_DAT_P: J8.3 R84.2 R86.1 U15.1(NC1) U15.6(A)
USB_SENSE: R84.1 TP17.1 U14.4(Y)
USB_VBUS: J8.1 R82.1 U14.2(A)
N20187524: TP3.1 U8.134(SCK_DCLK_MCLK)
N20187527: TP2.1 U8.135(WS_DR0)
N20187534: TP4.1 U8.136(I2S0_DL0)
N20187537: TP5.1 U8.137(I2S1_DR1)
N20187540: TP6.1 U8.138(I2S2_DL1)
N20187543: TP7.1 U8.139(I2S3_DR2)
N20187546: TP8.1 U8.140(SPDIF_DL2)

Not connected (* = marked no-connect by the designer): U8 8(QA0)* 9(QA1)* 24(QA12)* 25(QA13)* 40(QA24)* 41(QA25)* 53(NC)* 54(NC)* 55(NC)* 56(NC)* 57(NC)* 58(NC)* 59(NC)* 60(NC)* 61(NC)* 62(NC)* 63(NC)* 64(NC)* 65(NC)* 66(NC)*; U11 A17(NC)* A18(NC)* A19(NC)* A20(NC)* A22(NC)* B3(DNU)* B4(DNU)* B17(NC)* B18(NC)* B20(NC)* B21(NC)* B22(NC)* C18(NC)* C19(NC)* C20(NC)* C21(NC)* D19(NC)* D21(NC)* D22(NC)* E17(DNU)* E19(NC)* E20(NC)* E21(NC)* E22(NC)* F18(NC)* F19(NC)* F20(NC)* F22(NC)* G20(NC)* G21(NC)* G22(NC)* H20(NC)* H21(NC)* J21(NC)* J22(NC)* L9(DNU)* V11(NC)* Y6(NC)*; U13 A6(PM_BLSZ_0)* AB4(RESERVED)* AB10(RESERVED)* AD9(RESERVED)* AD11(RESERVED)* AD12(RESERVED)* AE9(RESERVED)* AE11(RESERVED)* AF11(RESERVED)* AF23(P_CLK3)* B6(PM_BLSZ_1)* B23(RESERVED)* C22(RESERVED)* F25(RESERVED)* N26(MOSCN)* T25(CTRL_ARSTZ)* U22(P2_VSYNC)* W24(P_DATAEN2)* W25(P_CLK2)* W26(P2_HSYNC)*; U43 A1(NC)* A8(NC)* C1(NC)* D1(NC)* E1(DNU)* F7(RFU)* G1(RFU)* H1(NC)* H8(NC)*; U44 11(4Y)* 12(4A)* 13(4B)*; U45 1(NC)*; X1 2* 4*

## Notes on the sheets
sheet 17
- Master Controller Flash Interface
- TI Information
           Selective Disclosure
  Property of Texas Instruments Only
sheet 18
- UART debug message port,
  not needed for production
- DNI
- Buffer to prevent host from detecting
  the USB slave before ARM finishes
  initialization
- Master Controller SSP0, UART0, USB, Reset, OSC
- TI Information
           Selective Disclosure
  Property of Texas Instruments Only
sheet 19
- Note: RC Filtering required
  only for
  TI reference design's flex
  cable
  due to impedance mismatch
- Master Controller Video Input, DMD & DAD Output
- TI Information
           Selective Disclosure
  Property of Texas Instruments Only
sheet 20
- COMPUTER GENERATED DRAWING - DO NOT REVISE MANUALLY
- NOTES, UNLESS OTHERWISE SPECIFIED:
- REVISIONS
- REV
- DESCRIPTION
- DATE
- APPROVED
- 1.
- The netname "P12V" represents connection to the +12V power plane.
- A
- ECO 2137507: Initial Release
- 11/1/2013
- NG
- 2.
- The netname "P3P3V" represents connection to the +3.3V power plane.
- 3.
- The netname "P1P8V" represents connection to the +1.8V digital power plane.
- B
- ECO 2140137: Updated to rev B
- 2/18/2014
- NG
- C
- ECO 2141055: Updated to rev C
- 4.
- The netname "P1P1V" represents connection to the +1.1V  power plane.
- 4/8/2014
- NG
- D
- ECO 2142175: Updated to rev D
- 5/28/2014
- NG
- 5.
- The netname "P1P8V_ITEA" represents connection to the +1.8V ITE6535 analog supply power plane.
- 6.
- The netname "F_VCCIO" represents connection to the +3V FPGA Vccio power plane.
- E
- ECO 2144118: Updated to rev E
- 8/8/2014
- NG
- F
- Updated to rev F
- 7.
- The netname "P2P5V_FAUXPLL" represents connection to the +2.5V FPGA aux/pll power plane.
- 11/7/2019
- DH
- G
- Updated to rev G
- 5/11/2020
- DH
- 8.
- The netname "P1P8V_A" represents connection to the +1.8V controller analog supply power plane.
- 9.
- The netname "GND" represents connection to the ground plane.
- 10.
- A "Z" suffix on a signal name indicates an active low signal.
- 11.
- All components with designators "U*", "Q*", and "D*" are electrostatic discharge sensitive.
- TI Information
           Selective Disclosure
  Property of Texas Instruments Only
- 2513535
- 0314PO
sheet 21
- Table of Contents
- Page
- Description
- 1
- Title
- 2
- Import Notice for TI Products
- 3
- Table Of Contents
- 4
- Block Diagram
- 5
- HDMI, DisplayPort Input/ESD
- 6
- IT6535 Input/Ouput Ports
- 7
- IT6535 Power/Ground Bypass
- 8
- Left/Right Split FPGA Bank 2A,3A,3B,4A
- 9
- Left/Right Split FPGA Bank 5A,5B,7A,8A
- 10
- Left/Right Split FPGA Configuration
- 11
- Left/Right Split FPGA Power/Ground Bypass
- 12
- Master Controller Video, DMD, DAD in/out ports
- 13
- Master Controller: USB, Reset/Clock, SSP0
- 14
- Master Controller: 128Mb x 3 flash interface
- 15
- Master Controller: JTAG, ICE interface
- 16
- Master Controller: I2C, Dual Controller ports, Trigger GPIOs
- 17
- Master Controller: Power/Ground Bypass
- 18
- Slave Controller: Video, DMD in/out ports
- 19
- Slave Controller: Reset/Clock Input, ICE, JTAG
- 20
- Slave Controller: 128Mb x 3 flash interface
- 21
- Slave Controller: I2C, Dual Controller, GPIOs
- 22
- Slave Controller: Power/Ground Bypass
- 23
- DMD Flex Connector
- 24
- Power Conv: 12V -->1.1V, 1.8V, 3.3V switchers
- 25
- Power Conv: FPGA Vccio, LDOs
- 26
- Input/output triggers, LED driver connector
- 27
- Posense, Powergood, 20MHz distribution
- 28
- External Parallel Connector
- 29
- Notes & Revision History
- TI Information
           Selective Disclosure
  Property of Texas Instruments Only
- Table of Contents
sheet 22
- I2C Ext
  Connector
  Page 16
- LED driver
  Conn
  Page 26
- Ext. Parallel
  Flash
  Page 14
- Ex Trigger
  Conn
  Page 26
- USB Jack &
  ESD Protection
  Page 13
- LED driver
  GPIO
  Page 16
- Ext Memory
  Interface
  Page 14
- Ext Trigger
  Interface
  Page 16
- I2C
  Page 16
- 3.3V
- FPGA
  Config
  Page 10
- Pwr/Gnd
  Bypass
  Page 17
- USB
  Page 13
- DisplayPort
  EDID
  Page 6
- HDMI EDID
  Page 5
- HDMI Type A
  Connector
  Page 5
- Left/Right Split FPGA
  Page 8,9,10,11
- Master
  Controller
  Pixel Data
- Odd/Even
  Pixel Input
  Page 12
- DLPC900
  Master
- DMD LVDS
  Data Out
  Page 12
- HDMI Receiver
  IT6535
  Page 6, 7
- DMD Flex
  Connection
  Page 23
- ESD
  Protection
  Page 5
- DisplayPort
  Connector
  Page 5
- Spare
  GPIOs
- GPIOs to
  FPGA
  Page 16
- Master
  Strap Pin
  Page 16
- DAD
  Control
  Page 12
- Slave
  Controller
  Pixel Data
- Powergood,
  Reset, Clk In
  Page 13
- Dual
  Controller
  Support
  Page 16
- SCP (SSP0)
  Interface
  Page 13
- ARM uP ICE
  Page 15
- Ext. Parallel
  Source Conn.
  Page 28
- TO
  FPGA
- DSTREAM Prog.
  Page 15
- 20MHz Osc
  Page 27
- Powergood,
  Reset, Clk In
  Page 19
- Dual
  Controller
  Support
  Page 21
- SCP (SSP0)
  Interface
  Page 19
- ARM uP ICE
  Page 19
- Odd/Even
  Pixel Input
  Page 18
- Pwr/Gnd
  Bypass
  Page 22
- 3.3V to 1.8V
  HDMI Rx Analog
- 3.3V to 2.5V
  FPGA Aux
- 12V to 3V
  FPGA IO
- DLPC900
  Slave
- DMD LVDS
  Data Out
  Page 18
- 12V Input
  Page 24
- 12V to 3.3V
- Slave
  Strap Pin
  Page 21
- POSENSE &
  PWRGOOD
  Generation
  Page 27
- 3.3V to 1.8V
  Controller
  Analog
- Ext Memory
  Interface
  Page 20
- 12V Monitor
- 12V to 1.1V
  Controller
  Core
- 1.1V Controller & FPGA Core
  1.8V digital
  1.8V Controller Analog
  1.8V HDMI Rx Analog
  2.5V FPGA Aux Pwr
  3.0V FPGA VCCio
  3.3V HDMI, IO power
- Ext. Parallel
  Flash
  Page 20
- 12V to 1.8V
- Power Conversion
  Page 24, 25
- Block Diagram
- TI Information
           Selective Disclosure
  Property of Texas Instruments Only
sheet 23
- Apply a crystal input
  even audio function
  is not used per ITE
  recommandation
- Must connect I2C and interrupt
  to controller for register setup
- I2C address select
  low = 0xB0
  high = 0xB2
- HDMI receiver input/output
- TI Information
           Selective Disclosure
  Property of Texas Instruments Only
sheet 24
- REVISION HISTORY
- Rev A
- PAGES - ALL
- Rev F
- - initial rev
- Added External Parallel Video Connector and 5V source
     Sheet 12:
        Added net HDMI_CEC to U13A,G23
     Sheet 28:
        Inserted Parallel Video Connector as Sheet 28. Revisions page moved to Sheet 29.
        Added U49
        Added J30, J31, J32
        Added R233, R234, R235, R236, R237, R238, R239, R240, R241, R249, R250, R251
        Added RP16, RP17, RP18
        Added C366, C373, C374, C376, C377
  Increased External Flash Memory to 128 MByte
   Sheet 14:
        Added net M_PM_ADDR_GPIO45 to U13F,U23
        Added net M_PM_ADDR_GPIO46 to U13F,T22
        Added net M_PM_ADDR_GPIO60 to U13F, H22
        Added net BUS_SELECT to U13I,H23
     Sheet 20:
        Added net S_PM_ADDR_GPIO45 to U22F,U23
        Added net S_PM_ADDR_GPIO45 to U22F,T22
        Added net S_PM_ADDR_GPIO60 to U22F, H22
     Sheet 14:
        Removed U16, U17, U18
        Removed R87, R88, R90, R96
        Removed C140, C141, C142, C143
        Added U43, U44, U45, U50
        Added C367, C368, C378, C379
        Added R252, R253, R254
     Sheet 20:
        Removed U23, U24, U25
        Removed R148, R149, R151, R157
        Removed C222, C223, C224, C225
        Added U46, U47, U48, U53
        Added C371, C372, C380, C381
        Added R255, R256, R257
  Addeded Connector for SSP1 Bus
       Added J33, R258, R259
- Rev B
- PAGE 27
- - new part for C360
- PAGE 26
- - relocated S_TP17 and S_TP18
- PAGE 24
- - new part for R179
- - removed C315, bulk cap not needed
- PAGE 25
- - new part for L4
- PAGE 10
- - new part for U12
- Rev C
- PAGES for U13 & U22
- - update pin name to match datasheet
- PAGE 15
- - add comments for usage of R117 & R118
- Rev D
- Remove references to DLPC910
- Rev E
- Updated U7
- Rev G
- Sheet 5
   - Changed J2 footprint to SMT
  Sheet 10
   - U12 changed to Micron MT25QL128ABA1ESE-0SIT
  Sheet 14
   - Added R260 and R261
   - Changed net connected to U44 pin 5 to M_PM_ADDR_GPIO45
  Sheet 20
   - Added R262 and R263
   - Changed net connected to U48 pin 2 to S_PM_CSZ2
- TI Information
           Selective Disclosure
  Property of Texas Instruments Only
sheet 25
- 3.3V IO
- Digital logic core
- DP analog frontend
- Logic power for analog frontend
- 3.3V HDMI RX analog frontend
- 1.8V HDMI RX analog frontend
- DP Rx PLL power
- Crystal and audio PLL
- HDMI Rx PLL power
- HDMI receiver Power / Gnd
- TI Information
           Selective Disclosure
  Property of Texas Instruments Only
sheet 26
- Left/Right Split FPGA Pwr/Gnd
- TI Information
           Selective Disclosure
  Property of Texas Instruments Only
